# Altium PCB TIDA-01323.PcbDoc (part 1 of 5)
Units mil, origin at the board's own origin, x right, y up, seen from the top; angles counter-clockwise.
Board outline 2467 x 6135 mil, 6 copper layers (Layer 1 - Top Layer, Layer 2 - GND, Layer 3 - Sensitive, Layer 4 - GND, Layer 5 - PWR, Layer 6 - Bottom Layer), stack 62.468 mil thick; 310 components, 202 nets, 881 pads, 527 vias.
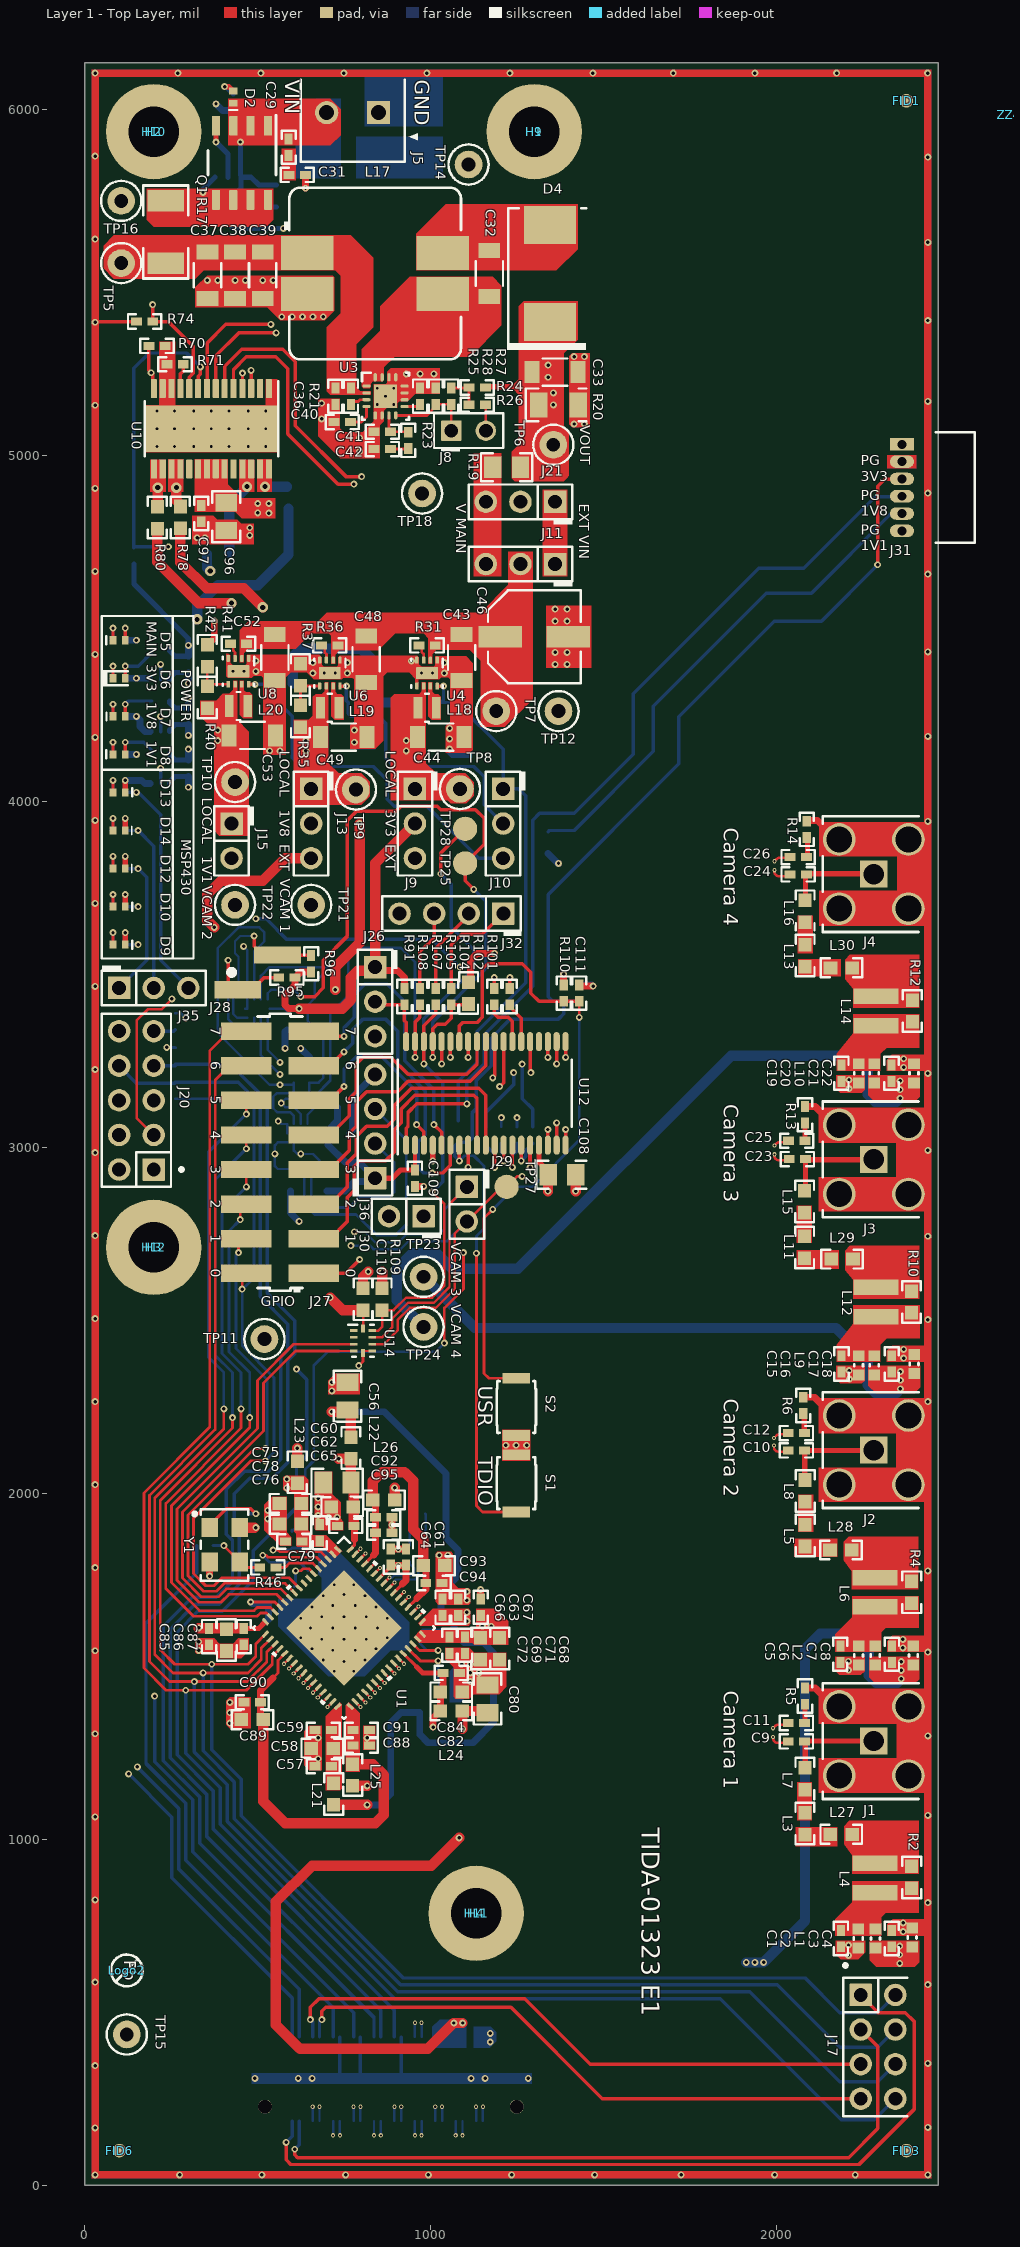
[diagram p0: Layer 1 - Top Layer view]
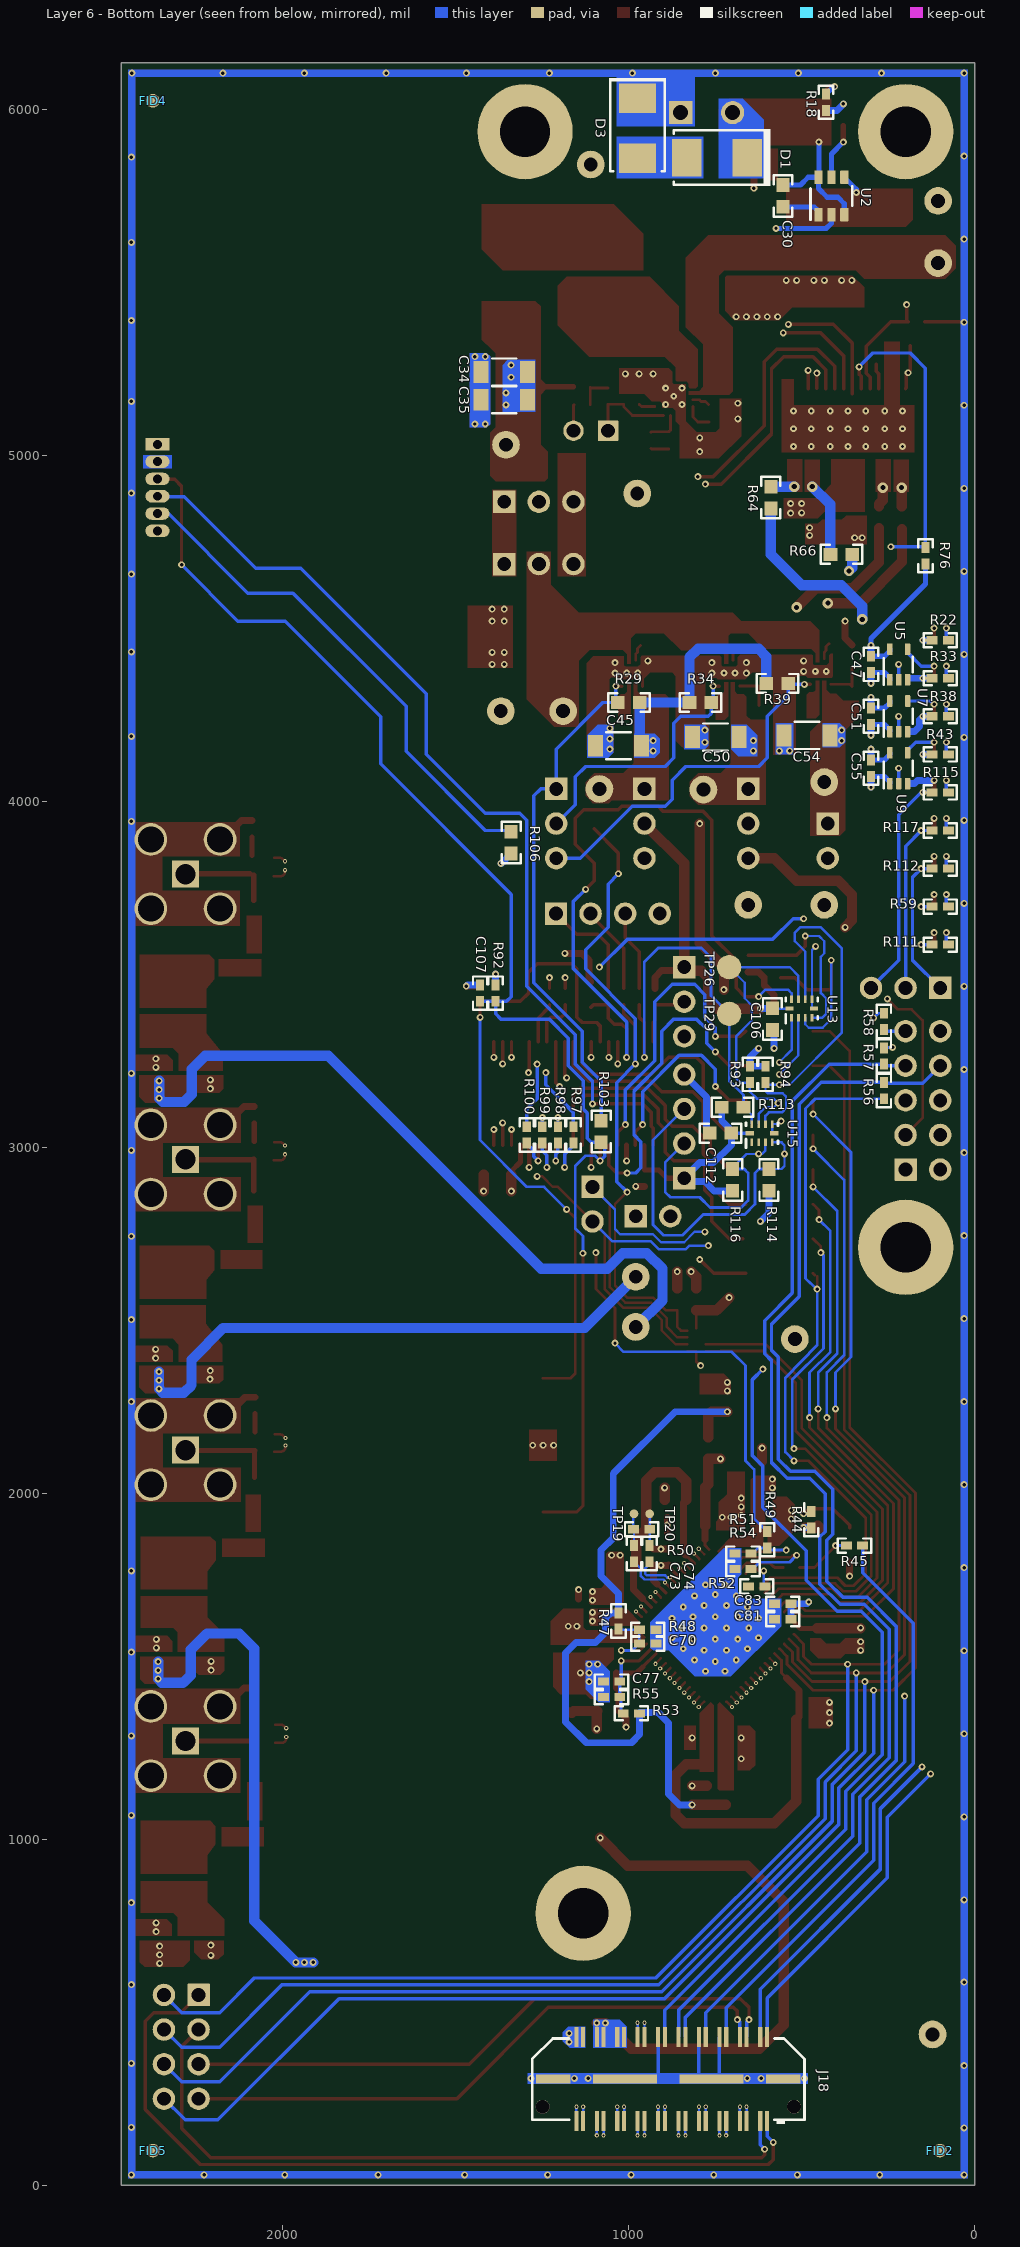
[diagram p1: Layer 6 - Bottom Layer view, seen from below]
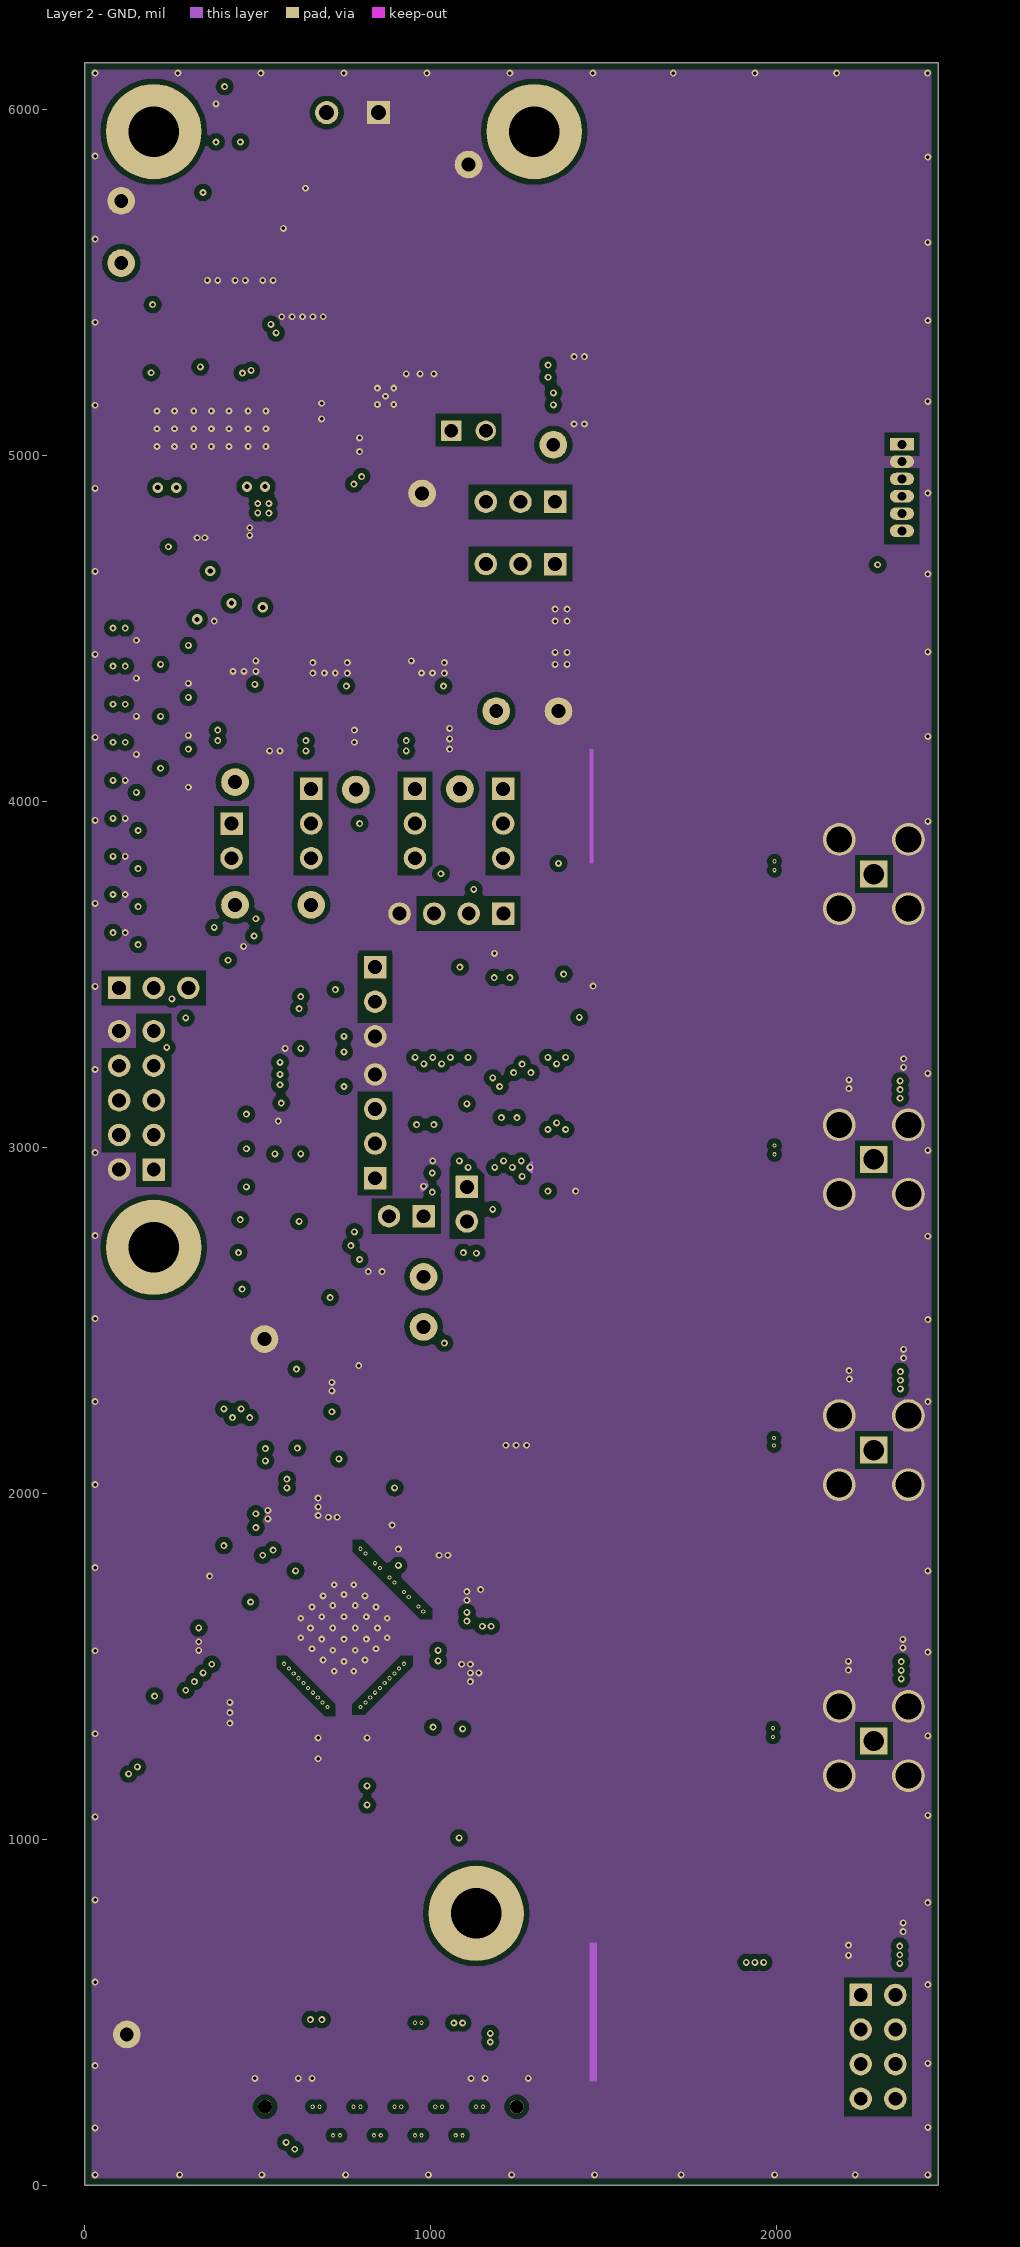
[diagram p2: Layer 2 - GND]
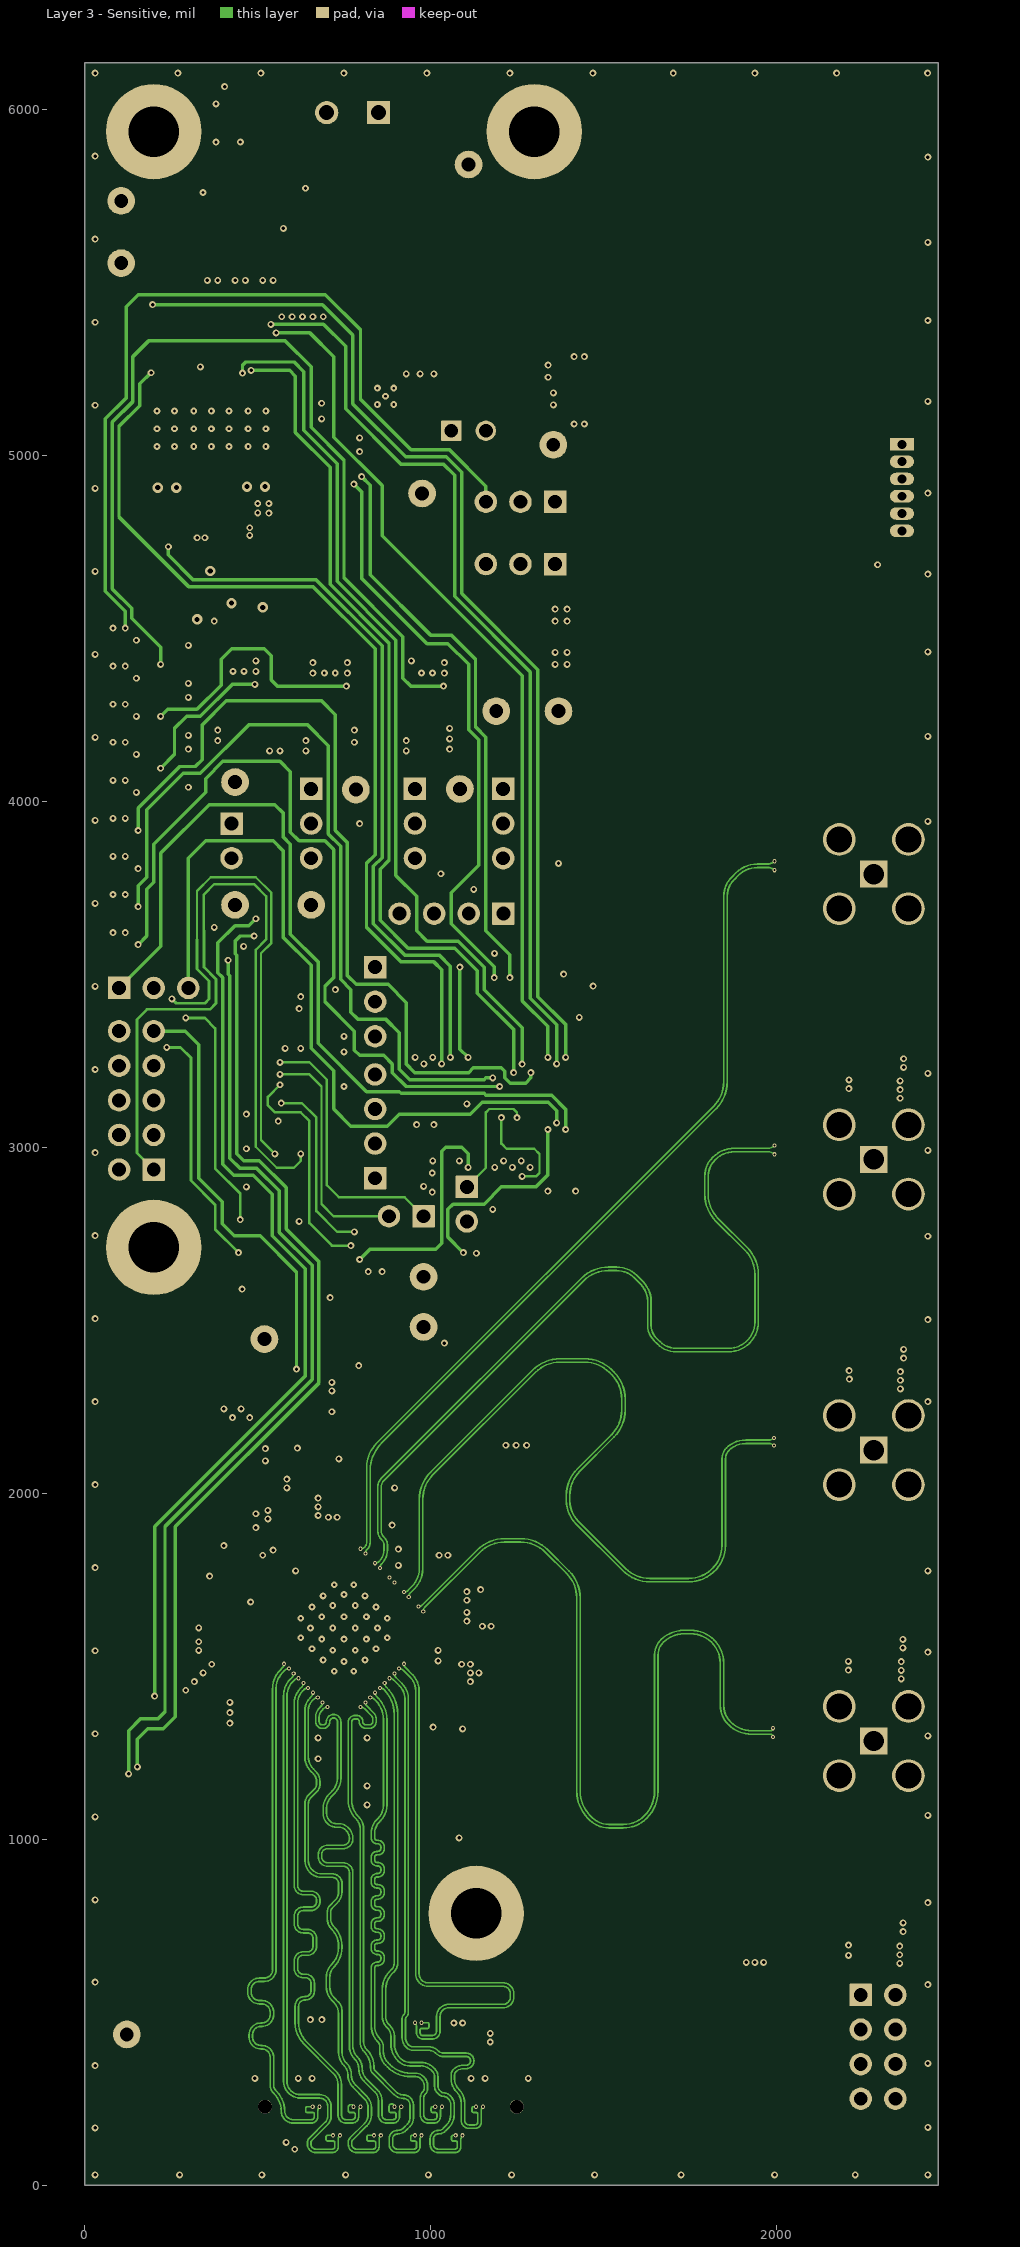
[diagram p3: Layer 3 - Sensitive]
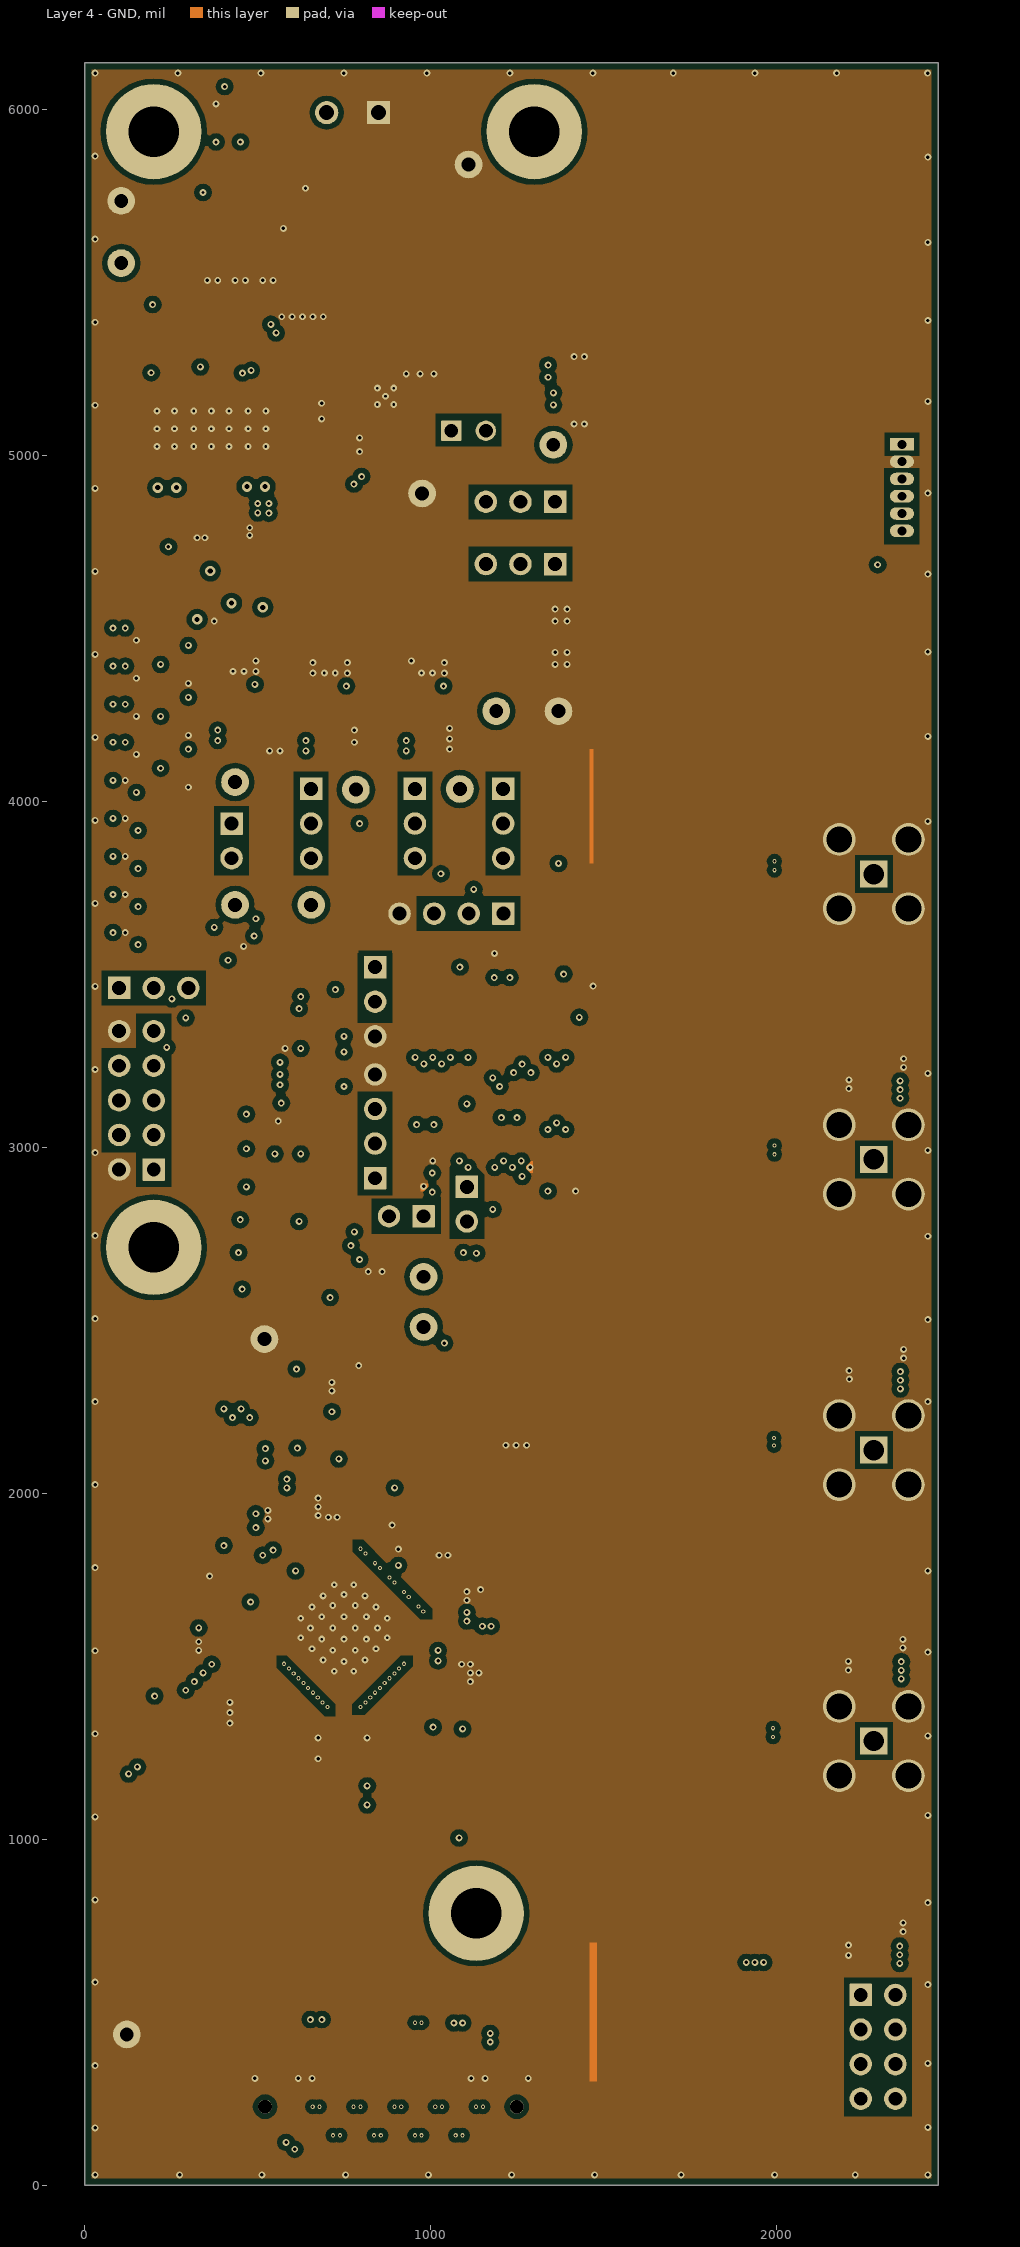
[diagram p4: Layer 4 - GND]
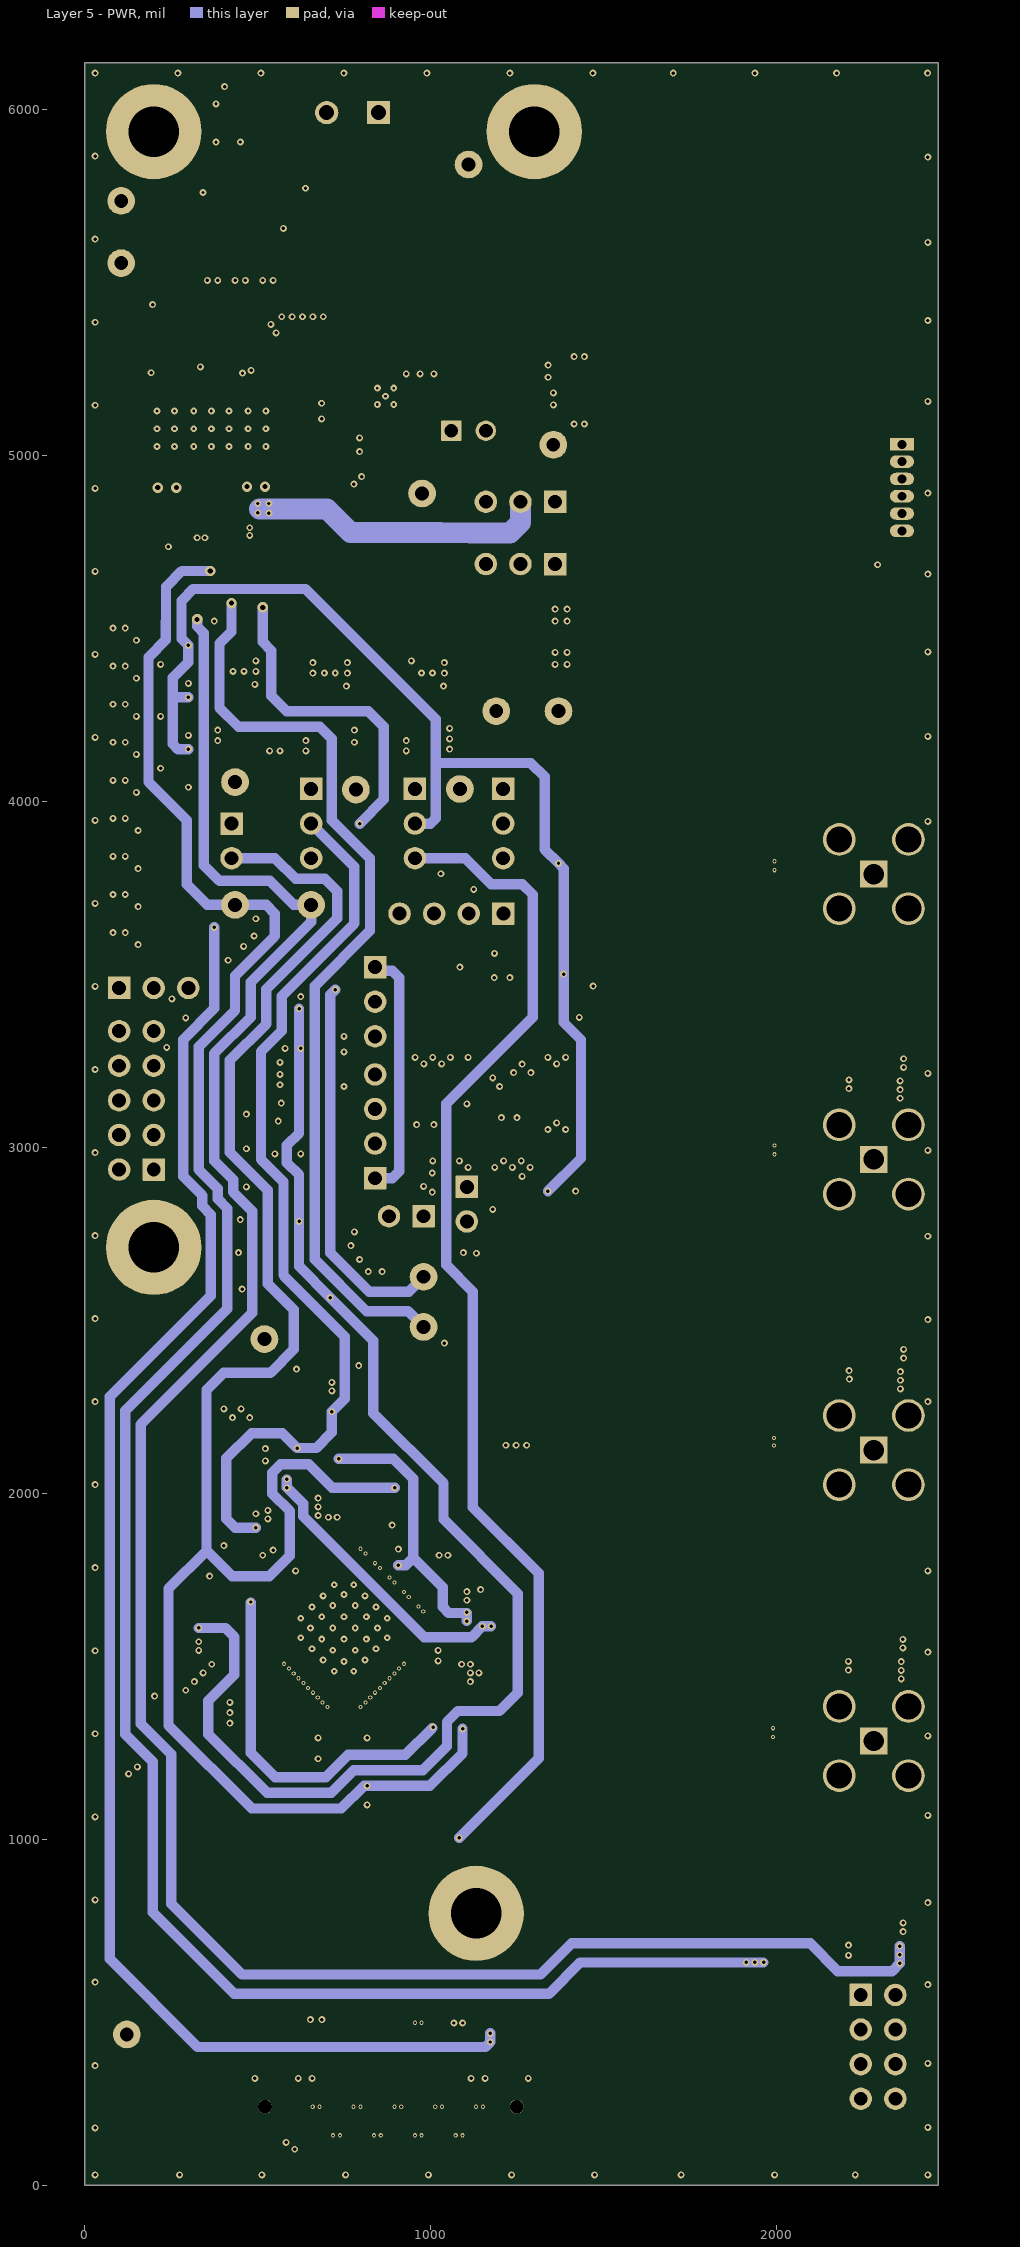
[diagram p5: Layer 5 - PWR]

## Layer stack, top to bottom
Top Solder: solder mask 0.4, Solder Resist, Dk 3.5
Layer 1 - Top Layer: signal copper 1.4
Dielectric 1: prepreg 10, 370HR, Dk 4.2
Layer 2 - GND: signal copper 1.417
Dielectric 2: core 7, 370HR, Dk 4.2
Layer 3 - Sensitive: signal copper 1.417
Dielectric 3: prepreg 20, 370HR, Dk 4.2
Layer 4 - GND: signal copper 1.417
Dielectric 4: core 7, 370HR, Dk 4.2
Layer 5 - PWR: signal copper 1.417
Dielectric 5: prepreg 10, 370HR, Dk 4.2
Layer 6 - Bottom Layer: signal copper 1.4
Bottom Solder: solder mask 0.4, Solder Resist, Dk 3.5

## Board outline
2467,6134 2467,0 0,0 0,6135 2467,6135 2467,6134

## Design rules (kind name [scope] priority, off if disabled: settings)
AcuteAngle [All] p1: minimum=4.50000000000000E+0001 checktracksonly=FALSE
AssemblyTestPointUsage [All] p1: valid=2
Clearance Clearance_Keepouts [((IsTrack Or IsArc) And Not InPoly) And IsFree and IsKeepOut vs ((IsTrack Or IsArc) And Not InPoly) And IsFree and IsKeepOut] p1: gap=0 ignorepadtopadclearanceinfootprint=FALSE
Clearance Clearance_Poly [InPolygon] p2: gap=15 ignorepadtopadclearanceinfootprint=FALSE except(0: Arc-Hole Track-Hole SMDPad-Hole THPad-Hole Via-Hole Fill-Hole Poly-Hole Region-Hole Text-Hole)
Clearance [All] p3: gap=4 ignorepadtopadclearanceinfootprint=FALSE except(0: Arc-Hole Track-Hole SMDPad-Hole THPad-Hole Via-Hole Fill-Hole Poly-Hole Region-Hole Text-Hole)
ComponentClearance ComponentClearance_MountingHoles_FiducialMarks [InComponentClass('Mounting Holes') vs InComponentClass('FiducialMark')] p1: gap=10 collisioncheckmode=3 verticalgap=10 showdistances=FALSE
ComponentClearance ComponentClearance_Shunt [InComponentClass('Header') vs InComponentClass('Shunt')] p2: gap=0 collisioncheckmode=3 verticalgap=0 showdistances=FALSE
ComponentClearance ComponentClearance_Logo [InComponentClass('Logo') vs InComponent('J17')] p3: gap=0 collisioncheckmode=3 verticalgap=0 showdistances=TRUE
ComponentClearance ComponentClearance_ScrewToNut [(HasFootprint('NY PMS 440 0025 PH'))  or (HasFootprint('CBTS140A')) vs (HasFootprint('Keystone_1902C'))  or (HasFootprint('29341'))] p4: gap=0 collisioncheckmode=3 verticalgap=0 showdistances=TRUE
ComponentClearance ComponentClearance_MountingHoles [InComponentClass('Mounting Holes')] p5: gap=250 collisioncheckmode=3 verticalgap=100000 showdistances=TRUE
ComponentClearance ComponentClearance_SmallPassives [HasFootprint('0201*') or HasFootprint('0402*') or HasFootprint('0508') or HasFootprint('0603*') or HasFootprint('0612') or HasFootprint('0805*') or HasFootprint('0815*') or HasFootprint('0830*') or HasFootprint('1206*') or HasFootprint('1210*') or HasFootprint('1808*') or HasFootprint('1812*') or HasFootprint('1825*') or HasFootprint('2010*') or HasFootprint('2220*') or HasFootprint('2225*') or HasFootprint('2512*') or HasFootprint('2728*') or HasFootprint('3518*') vs HasFootprint('0201*') or HasFootprint('0402*') or HasFootprint('0508') or HasFootprint('0603*') or HasFootprint('0612') or HasFootprint('0805*') or HasFootprint('0815*') or HasFootprint('0830*') or HasFootprint('1206*') or HasFootprint('1210*') or HasFootprint('1808*') or HasFootprint('1812*') or HasFootprint('1825*') or HasFootprint('2010*') or HasFootprint('2220*') or HasFootprint('2225*') or HasFootprint('2512*') or HasFootprint('2728*') or HasFootprint('3518*')] p6: gap=5 collisioncheckmode=3 verticalgap=10 showdistances=TRUE
ComponentClearance ComponentClearance_THtoSMT [IsThruComponent vs IsSMTComponent] p7: gap=10 collisioncheckmode=3 verticalgap=30 showdistances=TRUE
ComponentClearance ComponentClearance_THtoTH [IsThruComponent vs IsThruComponent] p8: gap=5 collisioncheckmode=3 verticalgap=30 showdistances=TRUE
ComponentClearance [All] p9: gap=5 collisioncheckmode=3 verticalgap=10 showdistances=TRUE
DiffPairsRouting [All] p1: maxlimit=25 minlimit=5 mostfreqgap=5 toplayer_minwidth=5 toplayer_maxwidth=7 toplayer_prefwidth=5 midlayer1_minwidth=5 midlayer1_maxwidth=7 midlayer1_prefwidth=5 midlayer2_minwidth=5 midlayer2_maxwidth=7 midlayer2_prefwidth=5 midlayer3_minwidth=5 midlayer3_maxwidth=7 midlayer3_prefwidth=5 midlayer4_minwidth=5 midlayer4_maxwidth=7 midlayer4_prefwidth=5 bottomlayer_minwidth=5 bottomlayer_maxwidth=7 bottomlayer_prefwidth=5 maxuncoupledlength=1000
FabricationTestPointUsage TestPointUsage [All] p1: valid=2 allowmultiple=FALSE
FabricationTestpoint Testpoint [All] p1: side=3 testpointundercomponent=TRUE minsize=40 maxsize=100 preferedsize=60 minholesize=0 maxholesize=40 preferedholesize=32 testpointgrid=1 allowsidetop=TRUE allowsidebottom=TRUE usegrid=TRUE gridtolerance=0.01
FanoutControl Fanout_LCC [IsLCC] p1: bgadir=Out bgaviamode=Centered fanoutstyle=Auto fanoutdirection=Alternating viagrid=1 // Fanout_LCC (Default Rule)
FanoutControl Fanout_BGA [IsBGA] p2: bgadir=Out bgaviamode=Centered fanoutstyle=Auto fanoutdirection=Alternating viagrid=1 // Fanout_BGA (Default Rule)
FanoutControl Fanout_Default [All] p4: bgadir=Out bgaviamode=Centered fanoutstyle=Auto fanoutdirection=Alternating viagrid=1 // Fanout_Default (Default Rule)
FanoutControl Fanout_Small [(CompPinCount < 5)] p5: bgadir=Out bgaviamode=Centered fanoutstyle=Auto fanoutdirection=OutThenIn viagrid=1 // Fanout_Small (Default Rule)
Height [All] p1: minheight=0 maxheight=2000 prefheight=500
HoleSize [All] p1: absolutevalues=TRUE maxlimit=251 minlimit=6 maxpercent=80.000 minpercent=20.000
MinimumAnnularRing MinimumAnnularRing_ThermalPadVias [IsVia and InAnyComponent] p1: minimumring=5.91
MinimumAnnularRing [All] p2: minimumring=3
MinimumSolderMaskSliver MinimumSolderMaskSliver_Logo [InComponentClass('Logo') vs InComponentClass('Logo')] p1: minsoldermaskwidth=0.7
MinimumSolderMaskSliver [All] p2: minsoldermaskwidth=3.94
PlaneConnect [All] p1: planeconnectstyle=Relief reliefexpansion=10 reliefentries=4 reliefconductorwidth=10 reliefairgap=10
PolygonConnect [All] p1: connectstyle=Direct reliefconductorwidth=10 reliefentries=4 polygonreliefangle="90 Angle" airgapwidth=10
RoutingVias ThermalPadVias [IsVia and InAnyComponent] p1: holewidth=7.87 width=19.68 viastyle="Through Hole" minholewidth=7.87 minwidth=19.68 maxholewidth=12.99 maxwidth=23.62
RoutingVias [All] p2: holewidth=16 width=34 viastyle="Through Hole" minholewidth=6 minwidth=12 maxholewidth=40 maxwidth=65
SilkToBoardRegionClearance [Not ((IsComment or IsDesignator) And (Hide <> 'False')) and not InRegion(1000,500,4000,800)] p1:
SilkToSilkClearance SilkToSilkClearance_Pb-FreeLogo [(HasFootprint('Pb-Free_Overlay_Medium') OR HasFootprint('Pb-Free_Overlay_Small')) vs (HasFootprint('Pb-Free_Overlay_Medium') OR HasFootprint('Pb-Free_Overlay_Small'))] p1: silktosilkclearance=0
SilkToSilkClearance [All] p2: silktosilkclearance=2
SilkToSolderMaskClearance SilkToComponentPadClearance [IsPad and InAnycomponent] p1: minsilkscreentomaskgap=2 clearancetoexposedcopper=TRUE
SilkToSolderMaskClearance "Silk to Solder Mask Opening" [All] p2: minsilkscreentomaskgap=3 clearancetoexposedcopper=FALSE
SolderMaskExpansion [All] p1: expansion=1.97
Width [All] p1: maxlimit=100 minlimit=6 preferedwidth=10 checkconnectedcopper=TRUE
14 further rules are at their usual default settings.

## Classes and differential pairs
component class V_Batt_Supply: C29 C30 C31 C32 C33 C34 C35 C36 C37 C38 C39 C40 C41 C42 D1 D2 D3 D4 D5 J5 J8 L17 Q1 R17 R18 R19 R20 R21 R22 R23 R24 R25 R26 R27 R28 TP5 TP6 U2 U3
component class uC: C106 C107 C108 C109 C110 C111 C112 D9 D10 D12 D13 D14 J26 J27 J28 J29 J30 J31 J32 J35 J36 R59 R91 R92 R93 R94 R95 R96 R97 R98 R99 R100 R101 R102 R103 R104 R105 R106 R107 R108 R109 R110 R111 R112 R113 R114 R115 R116 R117 S1 S2 TP25 TP26 TP27 TP28 TP29 U12 U13 U14 U15
component class Header: J8 J9 J10 J11 J13 J15 J17 J20 J21 J26 J27 J28 J29 J30 J32 J35 J36
component class Deserializer: C56 C57 C58 C59 C60 C61 C62 C63 C64 C65 C66 C67 C68 C69 C70 C71 C72 C73 C74 C75 C76 C77 C78 C79 C80 C81 C82 C83 C84 C85 C86 C87 C88 C89 C90 C91 C92 C93 C94 C95 L21 L22 L23 L24 L25 L26 R44 R45 R46 R47 R48 R49 R50 R51 R52 R53 R54 R55 TP19 TP20 U1 Y1
component class Connectors: J17 J18 J20 R56 R57 R58
component class Camera_Power: C96 C97 J21 R64 R66 R70 R71 R74 R76 R78 R80 TP21 TP22 TP23 TP24 U10
component class cam_connections: C1 C2 C3 C4 C5 C6 C7 C8 C9 C10 C11 C12 C15 C16 C17 C18 C19 C20 C21 C22 C23 C24 C25 C26 J1 J2 J3 J4 L1 L2 L3 L4 L5 L6 L7 L8 L9 L10 L11 L12 L13 L14 L15 L16 L27 L28 L29 L30 R1 R2 R4 R5 R6 R10 R12 R13 R14
component class Bucks: C43 C44 C45 C46 C47 C48 C49 C50 C51 C52 C53 C54 C55 D6 D7 D8 J9 J10 J11 J13 J15 L18 L19 L20 R29 R31 R33 R34 R35 R36 R37 R38 R39 R40 R41 R42 R43 TP7 TP8 TP9 TP10 TP11 TP12 TP14 TP15 TP16 TP18 U4 U5 U6 U7 U8 U9
component class Hardware: FID1 FID2 FID3 FID4 FID5 FID6 H1 H2 H3 H4 H9 H10 H11 H12 Logo2 ZZ2 ZZ3 ZZ4
component class FiducialMark: FID1 FID2 FID3 FID4 FID5 FID6
component class AssemblyNote: ZZ2 ZZ3 ZZ4
differential pair RIN3: +RIN3_P -RIN3_N
differential pair RIN2: +RIN2_P -RIN2_N
differential pair RIN1: +RIN1_P -RIN1_N
differential pair RIN0: +RIN0_P -RIN0_N
differential pair LPTX: +LPTX_P -LPTX_N
differential pair CSI1_D3: +CSI1_D3_P -CSI1_D3_N
differential pair CSI1_D2: +CSI1_D2_P -CSI1_D2_N
differential pair CSI1_D1: +CSI1_D1_P -CSI1_D1_N
differential pair CSI1_D0: +CSI1_D0_P -CSI1_D0_N
differential pair CSI1_CLK: +CSI1_CLK_P -CSI1_CLK_N
differential pair CSI0_D3: +CSI0_D3_P -CSI0_D3_N
differential pair CSI0_D2: +CSI0_D2_P -CSI0_D2_N
differential pair CSI0_D1: +CSI0_D1_P -CSI0_D1_N
differential pair CSI0_D0: +CSI0_D0_P -CSI0_D0_N
differential pair CSI0_CLK: +CSI0_CLK_P -CSI0_CLK_N

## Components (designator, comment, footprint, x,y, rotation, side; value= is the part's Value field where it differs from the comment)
C1 "C1005X7R1H104K050BB" 0402 2185.62,713.13 r270 top value=0.1uF
C2 "C1608X5R1E106M080AC" 0603L 2235.62,713.13 r270 top value=10uF
C3 "C1005X7R1H104K050BB" 0402 2332.62,713.13 r90 top value=0.1uF
C4 "C1608X5R1E106M080AC" 0603L 2391.62,716.13 r90 top value=10uF
C5 "C1005X7R1H104K050BB" 0402 2184,1535 r270 top value=0.1uF
C6 "C1608X5R1E106M080AC" 0603L 2237,1531 r270 top value=10uF
C7 "C1005X7R1H104K050BB" 0402 2333,1535 r90 top value=0.1uF
C8 "C1608X5R1E106M080AC" 0603L 2395,1531 r90 top value=10uF
C9 "CGA2B3X7R1H333K050BB" 0402 2057,1282.99 r180 top value=0.033uF
C10 "CGA2B3X7R1H333K050BB" 0402 2057,2124 r180 top value=0.033uF
C11 "CGA2B3X7R1H153K050BB" 0402 2057,1336 r180 top value=0.015uF
C12 "CGA2B3X7R1H153K050BB" 0402 2057,2174 r180 top value=0.015uF
C15 "C1005X7R1H104K050BB" 0402 2187.38,2373.87 r270 top value=0.1uF
C16 "C1608X5R1E106M080AC" 0603L 2237,2370 r270 top value=10uF
C17 "C1005X7R1H104K050BB" 0402 2332.38,2373.87 r90 top value=0.1uF
C18 "C1608X5R1E106M080AC" 0603L 2397.38,2373.87 r90 top value=10uF
C19 "C1005X7R1H104K050BB" 0402 2187,3214 r270 top value=0.1uF
C20 "C1608X5R1E106M080AC" 0603L 2237,3214.13 r270 top value=10uF
C21 "C1005X7R1H104K050BB" 0402 2332,3214 r90 top value=0.1uF
C22 "C1608X5R1E106M080AC" 0603L 2397,3214 r90 top value=10uF
C23 "CGA2B3X7R1H333K050BB" 0402 2059.94,2966 r180 top value=0.033uF
C24 "CGA2B3X7R1H333K050BB" 0402 2062,3789 r180 top value=0.033uF
C25 "CGA2B3X7R1H153K050BB" 0402 2058,3019.01 r180 top value=0.015uF
C26 "CGA2B3X7R1H153K050BB" 0402 2062,3839 r180 top value=0.015uF
C29 "CGA2B3X7R1H104M050BB" 0402 589.38,5890.87 r270 top value=0.1uF
C30 "GRM188R71A225KE15D" 0603 553.67,5750 r270 bottom value=2.2uF
C31 "CGA2B3X7R1H104M050BB" 0402 614.38,5810.87 r0 top value=0.1uF
C32 "C3216X7R1E475M160AC" 1206_190 1169.38,5525.87 r270 top value=4.7uF
C33 "C3216X7R1E475M160AC" 1206_190 1359.38,5240.87 r0 top value=4.7uF
C34 "C3216X7R1E475M160AC" 1206_190 1359.38,5240.87 r0 bottom value=4.7uF
C35 "C3216X7R1E475M160AC" 1206_190 1359.38,5160.87 r0 bottom value=4.7uF
C36 "GRM155R70J104KA01D" 0402 724.38,5170.87 r270 top
C37 "GRM31CR71E106KA12L" 1206_180 354.38,5520.87 r270 top value=10uF
C38 "GRM31CR71E106KA12L" 1206_180 434.38,5520.87 r270 top value=10uF
C39 "GRM31CR71E106KA12L" 1206_180 514.38,5520.87 r270 top value=10uF
C40 "GRM155R70J473KA01D" 0402 744.38,5096.36 r180 top
C41 "CC0402KRX7R9BB101" 0402 860.21,5068.37 r180 top value=100pF
C42 "GRM155R71C103KA01D" 0402 860.21,5018.37 r180 top
C43 "GRM31CR71C106KAC7L" 1206_180 1089.38,4415.87 r270 top value=10uF
C44 "GRM31CR61C226KE15L" 1206_180 1029.38,4185.87 r0 top value=22uF
C45 "GRM31CR61C226KE15L" 1206_180 1029.38,4160.87 r0 bottom value=22uF
C46 "EEE-FK1E470P" SM_RADIAL_D 1299.38,4475.87 r0 top value=47uF
C47 "C1005JB1V105K050BC" 0402 299.38,4395.87 r270 bottom value=1uF
C48 "GRM31CR71C106KAC7L" 1206_180 813.38,4410.87 r270 top value=10uF
C49 "GRM31CR61C226KE15L" 1206_180 748.38,4185.87 r0 top value=22uF
C50 "GRM31CR61C226KE15L" 1206_180 748.38,4185.87 r0 bottom value=22uF
C51 "C1005JB1V105K050BC" 0402 299.38,4245.87 r270 bottom value=1uF
C52 "GRM31CR71C106KAC7L" 1206_180 549.38,4415.87 r270 top value=10uF
C53 "GRM31CR61C226KE15L" 1206_180 484.38,4190.87 r0 top value=22uF
C54 "GRM31CR61C226KE15L" 1206_180 484.38,4190.87 r0 bottom value=22uF
C55 "C1005JB1V105K050BC" 0402 299.38,4095.87 r270 bottom value=1uF
C56 "CL21A106KAFN3NE" 0805_HV 759.38,2280.87 r90 top value=10uF
C57 "C1005JB1V105K050BC" 0402 689.38,1210.87 r180 top value=1uF
C58 "CGA2B3X7R1H104K050BB" 0603 686.38,1262.87 r180 top value=0.1uF
C59 "GCM155R71H103KA55D" 0402 689.38,1315.87 r180 top value=0.01uF
C60 "CL21A106KAFN3NE" 0805_HV 729.38,2030.87 r180 top value=10uF
C61 "C1005JB1V105K050BC" 0402 928.38,1815.87 r90 top value=1uF
C62 "CGA2B3X7R1H104K050BB" 0603 744.38,1960.87 r180 top value=0.1uF
C63 "GCM155R71H103KA55D" 0402 1079.38,1670.87 r90 top value=0.01uF
C64 "GCM155R71H103KA55D" 0402 884.38,1815.87 r90 top value=0.01uF
C65 "GCM155R71H103KA55D" 0402 754.38,1905.87 r180 top value=0.01uF
C66 "GCM155R71H103KA55D" 0402 1034.38,1670.87 r90 top value=0.01uF
C67 "C1005JB1V105K050BC" 0402 1144.38,1670.87 r90 top value=1uF
C68 "CGA2B3X7R1H104K050BB" 0603 1199.38,1550.87 r270 top value=0.1uF
C69 "GCM155R71H103KA55D" 0402 1099.38,1560.87 r270 top value=0.01uF
C70 "C1005X7R1H104K050BB" 0402 944.38,1565.87 r180 bottom value=0.1uF
C71 "CGA2B3X7R1H104K050BB" 0603 1144.38,1550.87 r270 top value=0.1uF
C72 "GCM155R71H103KA55D" 0402 1054.38,1560.87 r270 top value=0.01uF
C73 "CGA2B3X7R1H333K050BB" 0402 984.38,1825.95 r90 bottom value=0.033uF
C74 "CGA2B3X7R1H333K050BB" 0402 939.38,1825.95 r90 bottom value=0.033uF
C75 "CGA2B3X7R1H104K050BB" 0603 594.38,1970.87 r180 top value=0.1uF
C76 "GCM155R71H103KA55D" 0402 604.38,1860.87 r180 top value=0.01uF
C77 "C1005X7R1H104K050BB" 0402 1049.38,1455.87 r0 bottom value=0.1uF
C78 "CGA2B3X7R1H104K050BB" 0603 594.38,1910.87 r180 top value=0.1uF
C79 "GCM155R71H103KA55D" 0402 679.38,1885.87 r90 top value=0.01uF
C80 "CL21A106KAFN3NE" 0805_HV 1164.38,1405.87 r90 top value=10uF
C81 "C1005JB1V105K050BC" 0402 554.38,1635.87 r0 bottom value=1uF
C82 "CGA2B3X7R1H104K050BB" 0603 1059.38,1425.87 r0 top value=0.1uF
C83 "GCM155R71H103KA55D" 0402 554.38,1680.87 r0 bottom value=0.01uF
C84 "GCM155R71H103KA55D" 0402 1059.38,1480.87 r0 top value=0.01uF
C85 "C1005JB1V105K050BC" 0402 359.38,1585.87 r270 top value=1uF
C86 "CGA2B3X7R1H104K050BB" 0603 409.38,1575.87 r270 top value=0.1uF
C87 "GCM155R71H103KA55D" 0402 459.38,1585.87 r270 top value=0.01uF
C88 "C1005JB1V105K050BC" 0402 799.38,1270.87 r0 top value=1uF
C89 "CGA2B3X7R1H104K050BB" 0603 484.38,1345.87 r180 top value=0.1uF
C90 "GCM155R71H103KA55D" 0402 484.38,1395.87 r180 top value=0.01uF
C91 "GCM155R71H103KA55D" 0402 799.38,1315.87 r0 top value=0.01uF
C92 "C1005JB1V105K050BC" 0402 864.38,1930.87 r0 top value=1uF
C93 "CGA2B3X7R1H104K050BB" 0603 1009.38,1790.87 r0 top value=0.1uF
C94 "GCM155R71H103KA55D" 0402 1009.38,1740.87 r0 top value=0.01uF
C95 "GCM155R71H103KA55D" 0402 864.38,1885.87 r0 top value=0.01uF
C96 "CL21A106KAFN3NE" 0805_HV 409,4823 r270 top value=10uF
C97 "C1005X7R1H104K050BB" 0402 336.49,4832 r270 top value=0.1uF
C106 "0603YC104JAT2A" 0603 584.38,3370.87 r270 bottom value=0.1uF
C107 "UMK105B7222KV-F" 0402 1429.38,3445.87 r90 bottom value=2200pF
C108 "LMK212B7475KG-T" 0805_HV 1379.38,2920.87 r0 top value=4.7uF
C109 "GRM155R70J104KA01D" 0402 954.38,2910.87 r270 top
C110 "0603YC104JAT2A" 0603 804.38,2560.87 r90 top value=0.1uF
C111 "UMK105B7222KV-F" 0402 1429.38,3445.87 r90 top value=2200pF
C112 "0603YC104JAT2A" 0603 734.38,3040.87 r0 bottom value=0.1uF
D1 "SMBJ26A-13-F" SMB 744.38,5860.87 r0 bottom value=26V
D2 "SML-P12UTT86" SML-P1_RED 429.38,6035.87 r90 top value=Red
D3 "SMBJ14A-13-F" SMB 974.38,5945.87 r270 bottom value=14V
D4 "B360-13-F" SMC 1344.38,5525.87 r90 top
D5 "SML-P12PTT86" SML-P1_GREEN 99.38,4465.87 r0 top value=Green
D6 "SML-P12MTT86" SML-P1_YELLOW-GREEN 99.38,4355.87 r180 top value=Yellow/green
D7 "SML-P12YTT86" LED_SMLP12_Yellow 99.38,4245.87 r180 top value=Yellow
D8 "SML-P12PTT86" SML-P1_GREEN 99.38,4135.87 r0 top value=Green
D9 "SML-P12VTT86" SML-P1_RED 99.38,3585.87 r180 top value=Red
D10 "SMLP13BC8TT86" SML-P1_Blue 99.38,3695.87 r180 top value=Blue
D12 "SML-P12YTT86" LED_SMLP12_Yellow 99.38,3805.87 r0 top value=Yellow
D13 "SML-P12PTT86" SML-P1_GREEN 99.38,4025.87 r180 top value=Green
D14 "SML-P12DTT86" LED_SMLP12_ORANGE 99.38,3915.87 r0 top value=Orange
FID1 "Fiducial" Fiducial10-20 2375,6025 r0 top
FID2 "Fiducial" Fiducial10-20 100,100 r90 bottom
FID3 "Fiducial" Fiducial10-20 2375,100 r270 top
FID4 "Fiducial" Fiducial10-20 2375,6025 r90 bottom
FID5 "Fiducial" Fiducial10-20 2375,100 r90 bottom
FID6 "Fiducial" Fiducial10-20 100,100 r270 top
H1 "29341" 29341#1 1299.38,5935.87 r270 top locked
H2 "29341" 29341#1 199.38,5935.87 r270 top locked
H3 "29341" 29341#1 199.38,2710.87 r270 top
H4 "29341" 29341#2 1443,1266 r270 top locked
H9 "CBTS140A" CBTS140A 1299.38,5935.87 r270 top
H10 "CBTS140A" CBTS140A 199.38,5935.87 r270 top
H11 "CBTS140A" CBTS140A 1131.38,785.87 r270 top
H12 "CBTS140A" CBTS140A 199.38,2710.87 r270 top
J1 "59S20X-400L5-Y" Rosenberger_59S20X-400L5 2460,1284 r0 top
J2 "59S20X-400L5-Y" Rosenberger_59S20X-400L5 2460,2125 r0 top
J3 "59S20X-400L5-Y" Rosenberger_59S20X-400L5 2460,2965 r0 top
J4 "59S20X-400L5-Y" Rosenberger_59S20X-400L5 2460,3790 r0 top
J5 "1727010" PhoenixConact_1727010 774.38,5990.87 r180 top locked value=2x1
J8 "PEC02SAAN" CONN_PEC02SAAN 1109.38,5071.36 r0 top
J9 "TSW-103-07-G-S" TSW-103-07-G-S 954.38,3935.87 r270 top
J10 "TSW-103-07-G-S" TSW-103-07-G-S 1209.38,3935.87 r270 top
J11 "TSW-103-07-G-S" TSW-103-07-G-S 1259.38,4685.87 r180 top
J13 "TSW-103-07-G-S" TSW-103-07-G-S 654.38,3935.87 r270 top
J15 "TSW-102-07-G-S" TSW-102-07-G-S 424.38,3885.87 r270 top
J17 "TSW-104-07-G-D" TSW-104-07-G-D 2293,400 r270 top
J18 "QTH-020-04-L-D-DP-A" Samtec_QTH-020-01-L-D-DP-A 875.38,306.87 r0 bottom locked
J20 "TSW-105-07-G-D" TSW-105-07-G-D 149.38,3135.87 r90 top
J21 "TSW-103-07-G-S" TSW-103-07-G-S 1259.38,4865.87 r180 top
J26 "TSW-103-07-G-S" TSW-103-07-G-S 839.38,3420.87 r270 top
J27 "TSM-108-01-L-DV" Samtec_TSM-108-01-x-DV 564.38,2985.87 r180 top locked
J28 "TSM-102-01-L-SV" Samtec_TSM-102-01-L-SV 499.38,3505.87 r90 top
J29 "TSW-102-07-G-S" TSW-102-07-G-S 1104.38,2835.87 r270 top
J30 "TSW-102-07-G-S" TSW-102-07-G-S 929.38,2800.87 r180 top
J31 "851-43-006-20-001000" CONN_851-43-006-20-001000 2362,4907 r90 top
J32 "TSW-104-07-G-S" TSW-104-07-G-S 1059.88,3675.59 r180 top
J35 "TSW-103-07-G-S" TSW-103-07-G-S 199.38,3460.87 r0 top
J36 "TSW-104-07-G-S" TSW-104-07-G-S 839.38,3060.87 r90 top
L1 "BLM18AG102SN1D" 0603L 2285.62,713.13 r90 top value="1000 ohm"
L2 "BLM18AG102SN1D" 0603L 2285,1531 r90 top value="1000 ohm"
L3 "BLM18HE152SN1D" 0603 2081.62,1045.13 r270 top value="1500 ohm"
L4 "LQH3NPN100NG0" LQH3NP_G0 2284.62,888.13 r270 top value=10uH
L5 "BLM18HE152SN1D" 0603 2082.38,1877.87 r270 top value="1500 ohm"
L6 "LQH3NPN100NG0" LQH3NP_G0 2284.62,1714 r270 top value=10uH
L7 "BLM18HE152SN1D" 0603 2081.62,1175.13 r270 top value="1500 ohm"
L8 "BLM18HE152SN1D" 0603 2082.38,2006.87 r270 top value="1500 ohm"
L9 "BLM18AG102SN1D" 0603L 2282,2370 r90 top value="1000 ohm"
L10 "BLM18AG102SN1D" 0603L 2282,3214.13 r90 top value="1000 ohm"
L11 "BLM18HE152SN1D" 0603 2080.67,2711.03 r270 top value="1500 ohm"
L12 "LQH3NPN100NG0" LQH3NP_G0 2287,2553 r270 top value=10uH
L13 "BLM18HE152SN1D" 0603 2082,3554 r270 top value="1500 ohm"
L14 "LQH3NPN100NG0" LQH3NP_G0 2287,3394 r270 top value=10uH
L15 "BLM18HE152SN1D" 0603 2080.67,2843 r270 top value="1500 ohm"
L16 "BLM18HE152SN1D" 0603 2082,3682.48 r270 top value="1500 ohm"
L17 "DRQ127-2R2-R" DRQ127 839.38,5525.87 r0 top
L18 "VLS201610HBX-2R2M" VLS201610ET 989.38,4270.87 r180 top value=2.2uH
L19 "VLS201610HBX-2R2M" VLS201610ET 708.38,4270.87 r180 top value=2.2uH
L20 "VLS201610HBX-2R2M" VLS201610ET 444.38,4275.87 r180 top value=2.2uH
L21 "BLM18SG121TN1D" 0603 719.38,1130.87 r90 top value="120 ohm"
L22 "BLM18SG121TN1D" 0603 769.38,2130.87 r270 top value="120 ohm"
L23 "BLM18SG121TN1D" 0603 614.38,2060.87 r270 top value="120 ohm"
L24 "BLM18SG121TN1D" 0603 1059.38,1370.87 r180 top value="120 ohm"
L25 "BLM18SG121TN1D" 0603 774.38,1185.87 r90 top value="120 ohm"
L26 "BLM18SG121TN1D" 0603 864.38,1980.87 r180 top value="120 ohm"
L27 "BLM18HE152SN1D" 0603 2186.62,1014.13 r0 top value="1500 ohm"
L28 "BLM18HE152SN1D" 0603 2185.62,1836.13 r0 top value="1500 ohm"
L29 "BLM18HE152SN1D" 0603 2189,2677 r0 top value="1500 ohm"
L30 "BLM18HE152SN1D" 0603 2187,3519 r0 top value="1500 ohm"
Logo2 "Pb-Free Symbol" Pb-Free_Overlay_Small 121.51,620.87 r270 top
Q1 "SQ4850EY" SOIC-8 454.38,5845.87 r270 top value=60V
R2 "CRCW06034K02FKEA" 0603 2390,890 r270 top value=4.02k
R4 "CRCW06034K02FKEA" 0603 2390,1714 r270 top value=4.02k
R5 "CRCW040249R9FKED" 0402 2082,1414 r270 top value=49.9
R6 "CRCW040249R9FKED" 0402 2077,2254 r270 top value=49.9
R10 "CRCW06034K02FKEA" 0603 2389.64,2553 r270 top value=4.02k
R12 "CRCW06034K02FKEA" 0603 2392,3394 r270 top value=4.02k
R13 "CRCW040249R9FKED" 0402 2082,3094 r270 top value=49.9
R14 "CRCW040249R9FKED" 0402 2087,3919 r270 top value=49.9
R17 "CRCW20100000Z0EF" 2010 234.38,5645.87 r270 top value=0
R18 "CRCW04022K20JNED" 0402 429.38,6020.87 r90 bottom value=2.2k
R19 "CRCW08050000Z0EA" 0805_HV 1219.38,4965.87 r180 top value=0
R20 "CRCW1206100KJNEA" 1206 1369.38,5145.87 r180 top value=100K
R21 "CRCW040210K0JNED" 0402 769.38,5170.87 r270 top value=10K
R22 "CRCW04022K20JNED" 0402 99.38,4465.87 r180 bottom value=2.2k
R23 "CRCW04022K32FKED" 0402 935.21,5043.37 r90 top value=2.32k
R24 "CRCW040249R9FKED" 0402 1134.38,5196.36 r180 top value=49.9
R25 "CRCW040218K2FKED" 0402 969.38,5171.36 r270 top value=18.2k
R26 "CRCW040275K0FKED" 0402 1134.38,5146.36 r180 top value=75.0k
R27 "CRCW040286K6FKED" 0402 1059.38,5171.36 r90 top value=86.6k
R28 "CRCW040210K0FKED" 0402 1014.38,5171.36 r270 top value=10.0k
R29 "CRCW0603100KFKEA" 0603 999.38,4285.87 r180 bottom value=100k
R31 "CRCW040210K0JNED" 0402 989.38,4450.87 r0 top value=10k
R33 "CRCW0402360RJNED" 0402 99.38,4355.87 r0 bottom value=360
R34 "CRCW0603100KFKEA" 0603 792.61,4285.87 r180 bottom value=100k
R35 "CRCW0603124KFKEA" 0603 623.38,4245.87 r270 top value=124k
R36 "CRCW040210K0JNED" 0402 708.38,4450.87 r0 top value=10k
R37 "CRCW0603100KFKEA" 0603 623.38,4365.87 r270 top value=100k
R38 "CRCW0402470RJNED" 0402 99.38,4245.87 r180 bottom value=470
R39 "CRCW0603100KFKEA" 0603 570.14,4340.87 r180 bottom value=100k
R40 "CRCW060337K4FKEA" 0603 354.38,4300.87 r270 top value=37.4k
R41 "CRCW040210K0JNED" 0402 444.38,4455.87 r0 top value=10k
R42 "CRCW0603100KFKEA" 0603 354.38,4420.87 r270 top value=100k
R43 "CRCW0402220RJNED" 0402 99.38,4135.87 r180 bottom value=220
R44 "CRCW040210K0JNED" 0402 472,1923.45 r90 bottom value=10k
R45 "ERJ-2GE0R00X" 0402 347,1849 r180 bottom value=0
R46 "ERJ-2GE0R00X" 0402 529.38,1785.87 r180 top value=0
R47 "CRCW040213K3FKED" 0402 1029.38,1630.87 r90 bottom value=13.3k
R48 "CRCW040240K2FKED" 0402 944.38,1605.87 r0 bottom value=40.2k
R49 "CRCW04024K12FKED" 0402 599.38,1865.87 r90 bottom value=4.12k
R50 "CRCW0402100RFKED" 0402 962.38,1895.95 r0 bottom value=100
R51 "CRCW04024K99FKED" 0402 669.38,1825.87 r180 bottom value=4.99k
R52 "ERJ-2GE0R00X" 0402 629.38,1730.87 r0 bottom value=0
R53 "CRCW040282K5FKED" 0402 992,1364 r180 bottom value=82.5k
R54 "CRCW040210K0JNED" 0402 669.38,1780.87 r180 bottom value=10k
R55 "CRCW0402102KFKED" 0402 1049.38,1410.87 r180 bottom value=102k
R56 "ERJ-2GE0R00X" 0402 262,3164 r90 bottom value=0
R57 "ERJ-2GE0R00X" 0402 262,3264 r270 bottom value=0
R58 "ERJ-2GE0R00X" 0402 262,3364 r270 bottom value=0
R59 "CRCW0402220RJNED" 0402 99.38,3695.87 r0 bottom value=220
R64 "CRCW06030000Z0EA" 0603 589,4878 r90 bottom value=0
R66 "CRCW06030000Z0EA" 0603 385,4714 r0 bottom value=0
R70 "CRCW04024K70JNED" 0402 209,5316.5 r180 top value=4.7K
R71 "CRCW04021K30FKED" 0402 261,5263.49 r0 top value=1.30k
R74 "CRCW04021K20JNED" 0402 173,5387 r0 top value=1.2k
R76 "CRCW04022K20JNED" 0402 142,4710 r90 bottom value=2.2k
R78 "CRCW06030000Z0EA" 0603 276.29,4821 r90 top value=0
R80 "CRCW06030000Z0EA" 0603 209.81,4820 r90 top value=0
R91 "CRCW040210K0JNED" 0402 923.88,3435.87 r90 top value=10K
R92 "CRCW040210K0JNED" 0402 1384.38,3445.87 r90 bottom value=10K
R93 "CRCW04024K70JNED" 0402 649.38,3210.87 r90 bottom value=4.7K
R94 "CRCW04024K70JNED" 0402 604.38,3210.87 r90 bottom value=4.7K
R95 "CRCW04024K70JNED" 0402 584.38,3490.87 r0 top value=4.7K
R96 "CRCW04024K70JNED" 0402 654.38,3530.87 r270 top value=4.7K
R97 "CRCW04020000Z0ED" 0402 1159.38,3035.87 r270 bottom value=0
R98 "CRCW04020000Z0ED" 0402 1204.38,3035.87 r270 bottom value=0
R99 "CRCW04020000Z0ED" 0402 1249.38,3035.87 r270 bottom value=0
R100 "CRCW04020000Z0ED" 0402 1294.38,3035.87 r270 bottom value=0
R101 "CRCW04020000Z0ED" 0402 1228.62,3435.87 r270 top value=0
R102 "CRCW04020000Z0ED" 0402 1183.62,3435.87 r270 top value=0
R103 "CRCW06030000Z0EA" 0603 1079.38,3045.87 r90 bottom value=0
R104 "CRCW06034K70JNEA" 0603 1109.38,3445.87 r270 top value=4.7k
R105 "CRCW0402200RJNED" 0402 1059.38,3435.87 r90 top value=200
R106 "CRCW06030000Z0EA" 0603 1339.38,3880.87 r270 bottom value=0
R107 "CRCW0402200RJNED" 0402 1014.38,3435.87 r90 top value=200
R108 "CRCW0402200RJNED" 0402 968.88,3435.87 r90 top value=200
R109 "CRCW06034K70JNEA" 0603 859.38,2560.87 r270 top value=4.7k
R110 "CRCW040210K0JNED" 0402 1384.38,3445.87 r90 top value=10K
R111 "CRCW0402220RJNED" 0402 99.38,3585.87 r0 bottom value=220
R112 "CRCW0402487RFKED" 0402 99.38,3805.87 r0 bottom value=487
R113 "CRCW06034K70JNEA" 0603 699.38,3115.87 r0 bottom value=4.7k
R114 "CRCW06034K70JNEA" 0603 594.38,2905.87 r270 bottom value=4.7k
R115 "CRCW0402220RJNED" 0402 99.38,4025.87 r0 bottom value=220
R116 "CRCW06034K70JNEA" 0603 699.38,2905.87 r270 bottom value=4.7k
R117 "CRCW0402487RFKED" 0402 99.38,3915.87 r0 bottom value=487
S1 "SKRKAEE010" SW_SKRKAEE010 1247.38,2028.76 r90 top
S2 "SKRKAEE010" SW_SKRKAEE010 1247.38,2250 r270 top
TP5 "5000" Keystone5000 105.38,5555.87 r270 top value=Red
TP6 "5000" Keystone5000 1354.38,5030.87 r270 top value=Red
TP7 "5000" Keystone5000 1189.38,4260.87 r270 top value=Red
TP8 "5000" Keystone5000 1084.38,4035.87 r270 top value=Red
TP9 "5000" Keystone5000 783.75,4034.21 r270 top value=Red
TP10 "5000" Keystone5000 434.38,4055.87 r270 top value=Red
TP11 "5001" Keystone5001 519.38,2445.87 r270 top value=Black
TP12 "5001" Keystone5001 1369.38,4260.87 r270 top value=Black
TP14 "5001" Keystone5001 1109.38,5840.87 r270 top value=Black
TP15 "5001" Keystone5001 121.51,435.87 r270 top value=Black
TP16 "5001" Keystone5001 105.38,5735.87 r270 top value=Black
TP18 "5001" Keystone5001 975,4890 r90 top value=Black
TP19 "TP-025-SMT" TP_25MIL-SMT 984.38,1940.87 r0 bottom value=STD
TP20 "TP-025-SMT" TP_25MIL-SMT 939.38,1940.87 r0 bottom value=STD
TP21 "5000" Keystone5000 654.38,3700.87 r270 top value=Red
TP22 "5000" Keystone5000 434.38,3700.87 r270 top value=Red
TP23 "5000" Keystone5000 979.38,2625.87 r270 top value=Red
TP24 "5000" Keystone5000 979.38,2480.87 r270 top value=Red
TP25 "Pogo Pad" PogoPad 1099.38,3820.87 r270 top
TP26 "Pogo Pad" PogoPad 709.38,3520.87 r0 bottom
TP27 "Pogo Pad" PogoPad 1219.38,2885.87 r0 top
TP28 "Pogo Pad" PogoPad 1099.38,3920.87 r270 top
TP29 "Pogo Pad" PogoPad 709.38,3385.87 r90 bottom
U1 "DS90UB960TRGCRQ1" RGC0064G 749.38,1610.87 r315 top locked
U2 "LM74700QDDCRQ1" DDC0006A_N 413.93,5750 r90 bottom
U3 "TPS55340QRTERQ1" RTE0016C 869.38,5170.87 r0 top
U4 "TPS62162QDSGRQ1" DSG0008A 989.38,4370.87 r270 top
U5 "SN74LVC1G125DCKR" DCK0005A_N 219.38,4395.87 r90 bottom
U6 "TPS62160QDSGRQ1" DSG0008A 708.38,4370.87 r270 top
U7 "SN74LVC1G125DCKR" DCK0005A_N 219.38,4245.87 r90 bottom
U8 "TPS62160QDSGRQ1" DSG0008A 444.38,4375.87 r270 top
U9 "SN74LVC1G125DCKR" DCK0005A_N 219.38,4095.87 r90 bottom
U10 "TPS4H160BQPWPRQ1" PWP0028C_N 366,5077 r270 top
U12 "MSP430F2272TDAQ1" DA0038A_N 1159.38,3155.87 r90 top locked
U13 "TS3USB221AQRSERQ1" RSE0010A 499.38,3400.87 r90 bottom
U14 "TS3USB221AQRSERQ1" RSE0010A 804.38,2440.87 r0 top
U15 "TS3USB221AQRSERQ1" RSE0010A 614.38,3040.87 r90 bottom
Y1 "7C-25.000MCB-T" TXC_7C 404.38,1850.87 r0 top
ZZ2 "These assemblies are ESD sensitive, ESD precautions shall be observed." AssemblyNote 2872,5984 r270 top
ZZ3 "These assemblies must be clean and free from flux and all contaminants. Use of no clean flux is not acceptable." AssemblyNote 2772,5984 r270 top
ZZ4 "These assemblies must comply with workmanship standards IPC-A-610 Class 2, unless otherwise specified." AssemblyNote 2672,5984 r270 top

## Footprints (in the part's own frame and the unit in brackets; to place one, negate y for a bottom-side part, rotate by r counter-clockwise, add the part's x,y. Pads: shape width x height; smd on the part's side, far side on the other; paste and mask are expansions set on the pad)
0402 [mm] "0402 from SM-752 data"
  rect 0.8x0.6 smd: 1(-0.6,0) 2(0.6,0)
  silkscreen extent -1.22,-0.52 1.22,0.52, body extent -0.55,-0.3 0.55,0.3, height 0.6
0603 [mm] "0603 from SM-752 data"
  rect 1x0.95 smd: 1(-0.8,0) 2(0.8,0)
  silkscreen extent -1.52,-0.69 1.52,0.69, body extent -0.87,-0.47 0.87,0.47, height 1
0603L [mm] "0603 from SM-752 data"
  rect 0.8x0.85 smd: 1(-0.7,0) 2(0.7,0)
  silkscreen extent -0.07,-0.33 0.07,0.33, body extent -0.87,-0.47 0.87,0.47, height 1
0805_HV [mil] "0805 with 30mil clearance between pads"
  rect 50x63 smd: 1(-40,0) 2(40,0)
  silkscreen extent -74,-40 74,40, body extent -43,-29 43,29, height 57
1206 [mm] "1206 from SM-752 data"
  rect 1.3x1.85 smd: 1(-1.45,0) 2(1.45,0)
  silkscreen extent -2.03,-1.21 2.4,1.21, body extent -1.7,-0.9 1.7,0.9, height 1.35
1206_180 [mm] "1206_180"
  rect 1.1x1.6 smd: 1(-1.7,0) 2(1.7,0)
  silkscreen extent -0.9,-1 0.9,1, body extent -1.75,-0.95 1.75,0.95, height 1.8
1206_190 [mm] "1206_190"
  rect 1.1x1.6 smd: 1(-1.7,0) 2(1.7,0)
  silkscreen extent -0.9,-1 0.9,1, body extent -1.75,-0.95 1.75,0.95, height 1.9
2010 [mm] "Chip Capacitor, Body 5.08x2.54mm, IPC Medium Density"
  rect 1.6x2.7 smd: 1(-2.3,0) 2(2.3,0)
  silkscreen extent -3.42,-1.65 3.42,1.65, body extent -2.73,-1.45 2.73,1.45, height 1.66
29341#1 [mm] "MACHINE SCREW PAN SLOTTED M3"
  round 7 hole 3.7: ""(0,0)
  body extent -2.64,-2.64 2.76,2.76, height 1.71
29341#2 [mm] "MACHINE SCREW PAN SLOTTED M3"
  round 7 hole 3.7: ""(12.195,-7.915)
  body extent 9.45,-10.57 14.85,-5.17, height 1.71
AssemblyNote [mil] "Assembly Note"
CBTS140A [mil] "HEX STANDOFF M3 NYLON 40MM"
  body extent -109,-125 109,125
CONN_851-43-006-20-001000 [mil] "Mill-Max"
  rect 36x70 hole 26: 1(125,0)
  oval 36x70 hole 26: 2(75,0) 3(25,0) 4(-25,0) 5(-75,0) 6(-125,0)
  silkscreen extent -160,-210 160,-98, body extent -157,-210 157,8, height 87
CONN_PEC02SAAN [mm] "SULLINS"
  rrect7% 1.5x1.5 hole 1.016: 1(-1.27,0)
  round 1.5 hole 1.016: 2(1.27,0)
  silkscreen extent -2.54,-1.52 2.54,1.27, body extent -2.54,-1.27 2.54,1.27, height 8.38
DA0038A_N [mm] "TSOP, 38-Leads, Body 12.6x6.2mm (max), Pitch 0.65mm, IPC Medium Density"
  oval 1.4x0.45 smd: 1(-3.8,5.85) 2(-3.8,5.2) 3(-3.8,4.55) 4(-3.8,3.9) 5(-3.8,3.25) 6(-3.8,2.6) 7(-3.8,1.95) 8(-3.8,1.3) 9(-3.8,0.65) 10(-3.8,0) 11(-3.8,-0.65) 12(-3.8,-1.3) 13(-3.8,-1.95) 14(-3.8,-2.6) 15(-3.8,-3.25) 16(-3.8,-3.9) 17(-3.8,-4.55) 18(-3.8,-5.2) 19(-3.8,-5.85) 20(3.8,-5.85) 21(3.8,-5.2) 22(3.8,-4.55) 23(3.8,-3.9) 24(3.8,-3.25) 25(3.8,-2.6) 26(3.8,-1.95) 27(3.8,-1.3) 28(3.8,-0.65) 29(3.8,0) 30(3.8,0.65) 31(3.8,1.3) 32(3.8,1.95) 33(3.8,2.6) 34(3.8,3.25) 35(3.8,3.9) 36(3.8,4.55) 37(3.8,5.2) 38(3.8,5.85)
  silkscreen extent -4.45,-6.3 2.45,6.48, body extent -4.06,-6.25 4.06,6.25, height 1.2
DCK0005A_N [mm] "SOT353, 5-Leads, Body 2x1.3mm, Pitch 0.65mm, Lead Span 2.1mm, IPC Medium Density"
  rrect25% 0.85x0.4 smd: 1(-1.125,0.65) 2(-1.125,0) 3(-1.125,-0.65) 4(1.125,-0.65) 5(1.125,0.65)
  silkscreen extent -1.48,-1.02 0.55,1.1, body extent -1.14,-1 1.14,1, height 0.95
DDC0006A_N [mm]
  rrect17% 1x0.6 smd: 1(-1.375,0.95) 2(-1.375,0) 3(-1.375,-0.95) 4(1.375,-0.95) 5(1.375,0) 6(1.375,0.95)
  silkscreen extent -1.75,-1.52 0.7,1.53, body extent -1.43,-1.48 1.43,1.49, height 0.92
DRQ127 [mm] "COILTRONICS"
  rect 3.85x2.5 smd: 1(-4.975,1.5) 2(-4.975,-1.5) 3(4.975,-1.5) 4(4.975,1.5)
  silkscreen extent -6.7,-6.3 6.3,6.3, body extent -6.25,-6.25 6.25,6.25, height 8.01
DSG0008A [mm] "SON, 8-Leads, Body 2x2mm, Pitch 0.5mm, Thermal Pad 1.6x0.9mm, TI Recommended"
  rrect40% 0.5x0.25 smd: 1(-0.95,0.75) 2(-0.95,0.25) 3(-0.95,-0.25) 4(-0.95,-0.75) 5(0.95,-0.75) 6(0.95,-0.25) 7(0.95,0.25) 8(0.95,0.75)
  rrect11% 0.9x1.6 smd paste-0.45: 9(0,0)
  silkscreen extent -1.07,-1.15 1.07,1.15, body extent -1.05,-1.05 1.05,1.05, height 0.8
Fiducial10-20 [mm]
  round 1 smd mask+0.5: 1(0,0)
Keystone5000 [mil] "For Keystone 500x miniature loop terminals"
  round 80 hole 40: 1(0,0)
  silkscreen extent -58,-58 58,58, body extent -49,-49 49,49, height 182
Keystone5001 [mil] "For Keystone 500x miniature loop terminals"
  round 80 hole 40: 1(0,0)
  silkscreen extent -58,-58 58,58, body extent -49,-49 49,49, height 182
LED_SMLP12_ORANGE [mm] "Rohm Semiconductor"
  rect 0.5x0.6 smd mask+0.08: 1(-0.45,0) 2(0.45,0)
  silkscreen extent 0.92,-0.3 0.92,0.3, body extent -0.55,-0.35 0.55,0.35, height 0.25
LED_SMLP12_Yellow [mm] "Rohm Semiconductor"
  rect 0.5x0.6 smd mask+0.08: 1(-0.45,0) 2(0.45,0)
  silkscreen extent 0.92,-0.3 0.92,0.3, body extent -0.55,-0.35 0.55,0.35, height 0.25
LQH3NP_G0 [mm] "MURATA"
  rect 1.15x3.3 smd: 1(-1.075,0) 2(1.075,0)
  body extent -1.6,-1.6 1.6,1.6, height 1.01
Pb-Free_Overlay_Small [mil]
  silkscreen extent -46,-46 46,46
PhoenixConact_1727010 [mm]
  rect 1.7x1.7 hole 1.1: 1(-1.905,0)
  round 1.7 hole 1.1: 2(1.905,0)
  silkscreen extent -4.76,-2.41 3.81,3.6, body extent -3.81,-3.6 3.81,3.7, height 8.52
PogoPad [mil] "No Solder Paste"
  round 70 smd paste-35: 1(0,0)
PWP0028C_N [mm] "TSOP, 28-Leads, Body 9.7x4.4mm, Pitch 0.65mm, Exposed Pad, IPC Medium Density"
  rrect22% 1.4x0.45 smd: 1(-2.95,4.225) 2(-2.95,3.575) 3(-2.95,2.925) 4(-2.95,2.275) 5(-2.95,1.625) 6(-2.95,0.975) 7(-2.95,0.325) 8(-2.95,-0.325) 9(-2.95,-0.975) 10(-2.95,-1.625) 11(-2.95,-2.275) 12(-2.95,-2.925) 13(-2.95,-3.575) 14(-2.95,-4.225) 15(2.95,-4.225) 16(2.95,-3.575) 17(2.95,-2.925) 18(2.95,-2.275) 19(2.95,-1.625) 20(2.95,-0.975) 21(2.95,-0.325) 22(2.95,0.325) 23(2.95,0.975) 24(2.95,1.625) 25(2.95,2.275) 26(2.95,2.925) 27(2.95,3.575) 28(2.95,4.225)
  rrect3% 3.4x9.7 smd paste-1.7 mask-1.7: 29(0,0)
  rrect3% 3.1x5.18 on Top Paste: 29(0,0)
  rrect3% 3.1x5.18 on Top Solder: 29(0,0)
  silkscreen extent -3.5,-4.9 2,4.9, body extent -3.2,-4.85 3.2,4.85, height 1.13
RGC0064G [mm] "Texas Instruments"
  rrect42% 0.6x0.24 smd: 1(-4.4,3.75) 2(-4.4,3.25) 3(-4.4,2.75) 4(-4.4,2.25) 5(-4.4,1.75) 6(-4.4,1.25) 7(-4.4,0.75) 8(-4.4,0.25) 9(-4.4,-0.25) 10(-4.4,-0.75) 11(-4.4,-1.25) 12(-4.4,-1.75) 13(-4.4,-2.25) 14(-4.4,-2.75) 15(-4.4,-3.25) 16(-4.4,-3.75) 33(4.4,-3.75) 34(4.4,-3.25) 35(4.4,-2.75) 36(4.4,-2.25) 37(4.4,-1.75) 38(4.4,-1.25) 39(4.4,-0.75) 40(4.4,-0.25) 41(4.4,0.25) 42(4.4,0.75) 43(4.4,1.25) 44(4.4,1.75) 45(4.4,2.25) 46(4.4,2.75) 47(4.4,3.25) 48(4.4,3.75)
  rrect42% 0.24x0.6 smd: 17(-3.751,-4.4) 18(-3.251,-4.4) 19(-2.751,-4.4) 20(-2.251,-4.4) 21(-1.75,-4.4) 22(-1.25,-4.4) 23(-0.75,-4.4) 24(-0.25,-4.4) 25(0.25,-4.4) 26(0.75,-4.4) 27(1.25,-4.4) 28(1.75,-4.4) 29(2.251,-4.4) 30(2.751,-4.4) 31(3.251,-4.4) 32(3.751,-4.4) 49(3.751,4.4) 50(3.251,4.4) 51(2.751,4.4) 52(2.251,4.4) 53(1.75,4.4) 54(1.25,4.4) 55(0.75,4.4) 56(0.25,4.4) 57(-0.25,4.4) 58(-0.75,4.4) 59(-1.25,4.4) 60(-1.75,4.4) 61(-2.251,4.4) 62(-2.751,4.4) 63(-3.251,4.4) 64(-3.751,4.4)
  rrect2% 6x6 smd paste-3: 65(0,0)
  silkscreen extent -5.1,-5.1 5.1,5.1, body extent -4.57,-4.57 4.57,4.57, height 1.01
Rosenberger_59S20X-400L5 [mm] "Rosenberger"
  rect 2x2 hole 1.5 paste+0: 1(-4.55,0)
  round 2.4 hole 1.9 paste+0: MH1(-7.09,2.54) MH2(-2.01,2.54) MH3(-2.01,-2.54) MH4(-7.09,-2.54)
  silkscreen extent -8.3,-4.25 -1.27,4.25, body extent -8.3,-4.25 8.3,4.25, height 11.61
RSE0010A [mm] "QFN, 10-Leads, Body 1.5x2mm, Pitch 0.5mm, TI Recommended"
  rect 0.55x0.2 smd: 1(-0.675,0.75) 2(-0.675,0.25) 3(-0.675,-0.25) 4(-0.675,-0.75) 6(0.675,-0.75) 7(0.675,-0.25) 8(0.675,0.25) 9(0.675,0.75)
  rect 0.3x0.6 smd: 5(0,-0.9) 10(0,0.9)
  silkscreen extent -1.07,-1.17 0.77,1.18, body extent -0.77,-1.02 0.78,1.03, height 0.61
RTE0016C [mm] "Texas Insturments"
  oval 0.6x0.24 smd: 1(-1.4,0.75) 2(-1.4,0.25) 3(-1.4,-0.25) 4(-1.4,-0.75) 9(1.4,-0.75) 10(1.4,-0.25) 11(1.4,0.25) 12(1.4,0.75)
  oval 0.24x0.6 smd: 5(-0.75,-1.4) 6(-0.25,-1.4) 7(0.25,-1.4) 8(0.75,-1.4) 13(0.75,1.4) 14(0.25,1.4) 15(-0.25,1.4) 16(-0.75,1.4)
  rect 1.7x1.7 smd paste-0.85: 17(0,0)
  silkscreen extent -1.72,-1.73 1.72,1.73, body extent -1.57,-1.57 1.58,1.58, height 0.81
Samtec_QTH-020-01-L-D-DP-A [mm] "Receptacle, Differential, 0.5mm, 10x2, SMT"
  rect 0.3x1.45 smd: 1(-7,3.08) 2(-7,-3.09) 3(-6.5,3.08) 4(-6.5,-3.09) 5(-5.5,3.08) 6(-5.5,-3.09) 7(-5,3.08) 8(-5,-3.09) 9(-4,3.08) 10(-4,-3.09) 11(-3.5,3.08) 12(-3.5,-3.09) 13(-2.5,3.08) 14(-2.5,-3.09) 15(-2,3.08) 16(-2,-3.09) 17(-1,3.08) 18(-1,-3.09) 19(-0.5,3.08) 20(-0.5,-3.09) 21(0.5,3.08) 22(0.5,-3.09) 23(1,3.08) 24(1,-3.09) 25(2,3.08) 26(2,-3.09) 27(2.5,3.08) 28(2.5,-3.09) 29(3.5,3.08) 30(3.5,-3.09) 31(4,3.08) 32(4,-3.09) 33(5,3.08) 34(5,-3.09) 35(5.5,3.08) 36(5.5,-3.09) 37(6.5,3.08) 38(6.5,-3.09) 39(7,3.08) 40(7,-3.09)
  round 1.02 hole 1.02 unplated mask+0: MH1(-8.99,2.03) MH2(9.48,2.03)
  rect 2.54x0.64 smd: MP1(-8.19,0) MP4(8.7,0)
  rect 4.7x0.64 smd: MP2(-2.92,0) MP3(3.43,0)
  silkscreen extent -9.75,-2.98 10.25,3.3, body extent -9.75,-3.56 10.25,3.55, height 4.32
Samtec_TSM-102-01-L-SV [mm] "SAMTEC"
  rect 1.27x3.43 smd: 1(-1.27,1.46) 2(1.27,-1.46)
  silkscreen extent -0.2,1.7 0.2,2.1, body extent -2.53,-2.45 2.55,2.45, height 9.65
Samtec_TSM-108-01-x-DV [mm] "Header, 2.54mm, 8x2, SMT"
  rect 3.68x1.27 smd: 1(-2.475,8.89) 2(2.475,8.89) 3(-2.475,6.35) 4(2.475,6.35) 5(-2.475,3.81) 6(2.475,3.81) 7(-2.475,1.27) 8(2.475,1.27) 9(-2.475,-1.27) 10(2.475,-1.27) 11(-2.475,-3.81) 12(2.475,-3.81) 13(-2.475,-6.35) 14(2.475,-6.35) 15(-2.475,-8.89) 16(2.475,-8.89)
  silkscreen extent -1.65,-10.16 1.65,10.3, body extent -3.85,-10.16 3.85,10.16, height 9.65
SM_RADIAL_D [mm] "6.3 x 5.8mm:  Panasonic D"
  rect 3.2x1.6 smd: 1(-2.5,0) 2(2.5,0)
  silkscreen extent -3.4,-3.4 3.4,3.4, body extent -3.4,-3.4 3.4,3.4, height 6.1
SMB [mil] "Molded Diode, 2-Leads, Body 5.4x3.6mm, IPC Medium Density, based on OnSemi component dimensions"
  rect 85x107.99 smd: 1(-87.01,0) 2(87.01,0)
  silkscreen extent -155,-82 125,82, body extent -106,-71 106,71, height 91
SMC [mil] "Molded Diode, 2-Leads, Body 6.9x5.8mm, IPC Medium Density, based on OnSemi component dimensions and land patterns"
  rect 110x150 smd: 1(-140.49,0) 2(140.49,0)
  silkscreen extent -221,-105 189,123, body extent -156,-116 156,116, height 91
SML-P1_Blue [mm] "SMD, 2-Leads, Body 1x0.6mm"
  rect 0.5x0.6 smd: 1(-0.45,0) 2(0.45,0)
  silkscreen extent -0.95,-0.3 -0.95,0.3, body extent -0.52,-0.33 0.52,0.33, height 0.25
SML-P1_GREEN [mm] "ROHM"
  rect 0.5x0.6 smd: 1(-0.45,0) 2(0.45,0)
  silkscreen extent -0.95,-0.3 -0.95,0.3, body extent -0.53,-0.33 0.53,0.33, height 0.25
SML-P1_RED [mm] "ROHM"
  rect 0.5x0.6 smd: 1(-0.45,0) 2(0.45,0)
  silkscreen extent -0.95,-0.3 -0.95,0.3, body extent -0.52,-0.33 0.52,0.33, height 0.25
SML-P1_YELLOW-GREEN [mm] "Rohm Semiconductor"
  rect 0.5x0.6 smd: 1(-0.45,0) 2(0.45,0)
  silkscreen extent -0.63,-0.61 1.33,0.61, body extent -0.55,-0.35 0.55,0.35, height 0.25
SOIC-8 [mm] "duplicate of SO-8.  SOIC, 8-Leads, Body 5.0x4.0mm (max), Pitch 1.27mm, IPC Medium Density"
  rrect17% 1.45x0.6 smd: 1(-2.725,1.905) 2(-2.725,0.635) 3(-2.725,-0.635) 4(-2.725,-1.905) 5(2.725,-1.905) 6(2.725,-0.635) 7(2.725,0.635) 8(2.725,1.905)
  silkscreen extent -3.5,-2.5 0.9,2.5, body extent -3,-2.45 3,2.45, height 1.63
SW_SKRKAEE010 [mm] "Alps recommended land pattern"
  rect 0.8x2 smd: 1(-2.1,0) 2(2.1,0)
  silkscreen extent -1.9,-1.44 1.92,1.44, body extent -2.4,-1.45 2.4,1.45, height 1.96
TP_25MIL-SMT [mil]
  round 25 smd mask-2.5: 1(0,0)
TSW-102-07-G-S [mm] "Samtec 100mil, 1x2, 230 mil above insulator"
  rrect6% 1.65x1.65 hole 1.016: 1(-1.27,0)
  round 1.65 hole 1.016: 2(1.27,0)
  silkscreen extent -2.54,-1.27 2.54,1.65, body extent -2.54,-1.27 2.54,1.27, height 8.38
TSW-103-07-G-S [mm] "Samtec 100mil, 1x3, 230 mil above insulator"
  rect 1.65x1.65 hole 1.016: 1(-2.54,0)
  round 1.65 hole 1.016: 2(0,0) 3(2.54,0)
  silkscreen extent -3.81,-1.27 3.81,1.65, body extent -3.81,-1.27 3.81,1.27, height 8.38
TSW-104-07-G-D [mm] "Samtec 100mil, 2x4, 230 mil above insulator"
  rrect6% 1.65x1.65 hole 1.016: 1(-3.81,-1.27)
  round 1.65 hole 1.016: 2(-3.81,1.27) 3(-1.27,-1.27) 4(-1.27,1.27) 5(1.27,-1.27) 6(1.27,1.27) 7(3.81,-1.27) 8(3.81,1.27)
  silkscreen extent -6.1,-2.54 5.08,2.16, body extent -5.08,-2.54 5.08,2.54, height 8.38
TSW-104-07-G-S [mm] "Samtec 100mil, 1x4, 230 mil above insulator"
  rrect6% 1.65x1.65 hole 1.016: 1(-3.81,0)
  round 1.65 hole 1.016: 2(-1.27,0) 3(1.27,0) 4(3.81,0)
  silkscreen extent -5.16,-1.27 5.08,1.65, body extent -5.08,-1.27 5.08,1.27, height 8.38
TSW-105-07-G-D [mm] "Samtec 100mil, 2x5, 230 mil above insulator"
  rrect6% 1.65x1.65 hole 1.016: 1(-5.08,-1.27)
  round 1.65 hole 1.016: 2(-5.08,1.27) 3(-2.54,-1.27) 4(-2.54,1.27) 5(0,-1.27) 6(0,1.27) 7(2.54,-1.27) 8(2.54,1.27) 9(5.08,-1.27) 10(5.08,1.27)
  silkscreen extent -6.35,-3.43 6.35,2.54, body extent -6.35,-2.54 6.35,2.54, height 8.38
TXC_7C [mm] "TXC"
  rect 1.2x1.4 smd: 1(-1.1,1.27) 2(-1.1,-1.27) 3(1.1,-1.27) 4(1.1,1.27)
  silkscreen extent -2.32,-2.63 1.73,2.63, body extent -1.7,-2.6 1.7,2.6, height 1.4
VLS201610ET [mm] "TDK"
  rect 0.65x1.6 smd: 1(-0.675,0) 2(0.675,0)
  silkscreen extent -0.15,-1.02 0.15,1.02, body extent -1.05,-0.85 1.05,0.85, height 0.95

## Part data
C1 C3 C5 C7 C15 C17 C19 C21: "CAP, CERM, 0.1 µF, 50 V, +/- 10%, X7R, 0402", Cap_Case=0402, Manufacturer=TDK, Supplier Part Number 1=445-5932-1-ND, TempCo=X7R, Tolerance_%=10, Value1=Unknown, Value2=50V, ValueDisplayed=0.1µF
C2 C4 C6 C8 C16 C18 C20 C22: "CAP, CERM, 10 µF, 25 V, +/- 20%, X5R, 0603", Cap_Case=0603, Manufacturer=TDK, Supplier Part Number 1=445-9015-1-ND, TempCo=X5R, Tolerance_%=20, Value1="0.004639 ohm", Value2=25V, ValueDisplayed=10µF
C9 C10 C23 C24: "CAP, CERM, 0.033 µF, 50 V, +/- 10%, X7R, AEC-Q200 Grade 1, 0402", Cap_Case=0402, Manufacturer=TDK, Supplier Part Number 1=445-6896-1-ND, TempCo=X7R, Tolerance_%=10, Value1="0.098477 ohm", Value2=50V, ValueDisplayed=0.033µF
C11 C12 C25 C26: "CAP, CERM, 0.015 µF, 50 V,+/- 10%, X7R, AEC-Q200 Grade 1, 0402", Cap_Case=0402, Manufacturer=TDK, Supplier Part Number 1=445-6894-1-ND, TempCo=X7R, Tolerance_%=10, Value1="0.2162 ohm", Value2=50V, ValueDisplayed=0.015µF
C29 C31: "CAP, CERM, 0.1 µF, 50 V, +/- 20%, X7R, AEC-Q200 Grade 1, 0402", Cap_Case=0402, Manufacturer=TDK, Supplier Part Number 1=445-12271-1-ND, TempCo=X7R, Tolerance_%=20, Value1=Unknown, Value2=50V, ValueDisplayed=0.1µF
C30: "CAP, CERM, 2.2 µF, 10 V, +/- 10%, X7R, 0603", Cap_Case=0603, Manufacturer=MuRata, Supplier Part Number 1=490-4520-1-ND, TempCo=X7R, Tolerance_%=10, Value1="0.009 ohm", Value2=10V, ValueDisplayed=2.2µF
C32 C33 C34 C35: "CAP, CERM, 4.7 µF, 25 V, +/- 20%, X7R, 1206_190", Cap_Case=1206, Manufacturer=TDK, Supplier Part Number 1=445-1424-1-ND, TempCo=X7R, Tolerance_%=20, Value1=Unknown, Value2=25V, ValueDisplayed=4.7µF
C36 C109: "Cap, Cer-X7R, 0.1uF, 6.3V, 10%, 0402", Cap_Case=0402, Manufacturer=MuRata, Supplier Part Number 1=GRM155R70J104KA01D-ND, TempCo=X7R, Tolerance_%=10, Value1=Unknown, Value2=6.3V, ValueDisplayed=0.1µF
C37 C38 C39: "CAP, CERM, 10 µF, 25 V, +/- 10%, X7R, 1206", Cap_Case=2220, Manufacturer=MuRata, Supplier Part Number 1=81-GRM31CR71E106KA12, TempCo=X7R, Tolerance_%=10, Value1=Unknown, Value2=25V, ValueDisplayed=10µF
C40: "Cap, Cer-X7R, 0.047uF, 6.3V, 10%, 0402", Cap_Case=0402, Manufacturer=MuRata, Supplier Part Number 1=GRM155R70J473KA01D-ND, TempCo=X7R, Tolerance_%=10, Value1=Unknown, Value2=6.3V, ValueDisplayed=0.047µF
C41: "Cap, Cer-X7R, 100pF, 50V, 10%, 0402", Cap_Case=0402, Manufacturer="Yageo America", PART Name=SCH_LIB\CAP_NP, Supplier Part Number 1=311-1419-1-ND, TempCo=X7R, Tolerance_%=10, Value1=Unknown, Value2=50V, ValueDisplayed=100pF
C42: "Cap, Cer-X7R, 10000pF, 16V, 10%, 0402", Cap_Case=0402, Manufacturer=MuRata, Supplier Part Number 1=490-1313-1-ND, TempCo=X7R, Tolerance_%=10, Value1=Unknown, Value2=16V, ValueDisplayed=0.01µF
C43 C48 C52: "CAP, CERM, 10 µF, 16 V, +/- 10%, X7R, 1206", Cap_Case=1206, Manufacturer=MuRata, Supplier Part Number 1=490-3911-1-ND, TempCo=X7R, Tolerance_%=10, Value1=Unknown, Value2=16V, ValueDisplayed=10µF
C44 C49 C53: "CAP, CERM, 22 µF, 16 V, +/- 10%, X5R, 1206", Cap_Case=1206, Manufacturer=MuRata, Supplier Part Number 1=GRM31CR61C226KE15L-ND, TempCo=X5R, Tolerance_%=10, Value1=Unknown, Value2=16V, ValueDisplayed=22µF
C45 C50 C54: "CAP, CERM, 22 µF, 16 V, +/- 10%, X5R, 1206", Cap_Case=1206, Manufacturer=MuRata, Supplier Part Number 1=GRM31CR61C226KE15L-ND, TempCo=X5R, Tolerance_%=10, Value1=Unknown, Value2=16V, ValueDisplayed=open
C46: "CAP, AL, 47 µF, 25 V, +/- 20%, 0.36 ohm, SMD", Cap_Case=D, Manufacturer=Panasonic, Supplier Part Number 1=PCE3804CT-ND, Tolerance_%=20, Value1="0.36 ohm", Value2=25V, ValueDisplayed=47µF
C47 C51 C55 C57 C61 C67 C81 C85 C88 C92: "CAP, CERM, 1 µF, 35 V, +/- 10%, JB, 0402", Cap_Case=0402, Manufacturer=TDK, Supplier Part Number 1=445-11014-1-ND, TempCo=JB, Tolerance_%=10, Value1=Unknown, Value2=35V, ValueDisplayed=1µF
C56 C60 C80 C96: "CAP, CERM, 10 µF, 25 V, +/- 10%, X5R, 0805", Cap_Case=0805, Manufacturer=Samsung, Supplier Part Number 1=1276-2890-1-ND, TempCo=X5R, Tolerance_%=10, Value1=Unknown, Value2=25V, ValueDisplayed=10µF
C58 C62 C68 C71 C75 C78 C82 C86 C89 C93: library part GRM188R71C474KA88D, "CAP, CERM, 0.1uF, 50V, +/-10%, X7R, 0402", Cap_Case=0402, Manufacturer=TDK, Supplier Part Number 1=445-6899-1-ND, TempCo=X7R, Tolerance_%=10, Value1=Unknown, Value2=50V, ValueDisplayed=0.1µF
C59 C63 C64 C65 C66 C69 C72 C76 C79 C83 C84 C87 C90 C91 C94 C95: "CAP, CERM, 0.01uF, 50V, +/-10%, C0G/NP0, 0402", Cap_Case=0402, Manufacturer=MuRata, Supplier Part Number 1=490-4762-1-ND, TempCo=C0G/NP0, Tolerance_%=10, Value1=Unknown, Value2=50V, ValueDisplayed=0.01µF
C70 C77 C97: "CAP, CERM, 0.1 µF, 50 V, +/- 10%, X7R, 0402", Cap_Case=0402, Manufacturer=TDK, Supplier Part Number 1=445-5932-1-ND, TempCo=X7R, Tolerance_%=10, Value1="0.039064 ohm", Value2=50V, ValueDisplayed=0.1µF
C73 C74: "CAP, CERM, 0.033 µF, 50 V, +/- 10%, X7R, 0402", Cap_Case=0402, Manufacturer=TDK, Supplier Part Number 1=445-6896-1-ND, TempCo=X7R, Tolerance_%=10, Value1=Unknown, Value2=50V, ValueDisplayed=0.033µF
C106 C110 C112: "CAP, CERM, 0.1uF, 16V, +/-5%, X7R, 0603", Cap_Case=0603, Manufacturer=AVX, Supplier Part Number 1=478-3726-1-ND, TempCo=X7R, Tolerance_%=5, Value1="0.039 ohm", Value2=16V, ValueDisplayed=0.1µF
C107 C111: library part Capacitor, "Cap, Cer-X7R, 2200pF, 50V, 10%, 0402", Alternate Manufacturer=-, Manufacturer="Taiyo Yuden", Operating Temperature="-55°C ~ 125°C", PART Name=SCH_LIB\CAP_NP, Supplier Part Number 1=587-1221-1-ND, TempCo=X7R, Tolerance_%=±10%
C108: "Cap, Cer-X7R, 4.7uF, 10V, 10%, 0805", Cap_Case=0805, Manufacturer="Taiyo Yuden", PART Name=SCH_LIB\CAP_NP, Supplier Part Number 1=587-1442-1-ND, TempCo=X7R, Tolerance_%=10, Value1=Unknown, Value2=10V, ValueDisplayed=4.7µF
D1: "Diode, TVS, Uni, 26 V, 600 W, SMB", Manufacturer="Diodes Inc.", Power_W=5, Supplier Part Number 1=SMBJ26A-FDICT-ND, Value1=5W
D2: "LED, Red, SMD", Color=red, Manufacturer=Rohm, Supplier Part Number 1=511-1593-1-ND, Value1=W, Value2=2V
D3: "Diode, TVS, Uni, 14 V, 600 W, SMB", Manufacturer="Diodes Inc.", Power_W=5, Supplier Part Number 1=SMBJ14A-FDICT-ND, Value1=5W
D4: "Diode, Schottky, 3A, 60V, SMC", Manufacturer="Diodes Inc.", Supplier Part Number 1=B360-FDICT-ND, Value1=3A, Value2=0.7V
D5 D8 D13: "LED, Green, SMD", Color=green, Manufacturer=Rohm, Supplier Part Number 1=511-1592-1-ND, Value1=W, Value2=2.2V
